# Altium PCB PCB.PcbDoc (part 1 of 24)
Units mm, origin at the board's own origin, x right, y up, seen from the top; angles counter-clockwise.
Board outline 100 x 160 mm, 10 copper layers (TOP_L1, L2, L3, L4, L5, L6, L7, L8, L9, BOTTOM_L10), stack 1.946 mm thick; 1358 components, 1149 nets, 6777 pads, 10914 vias.
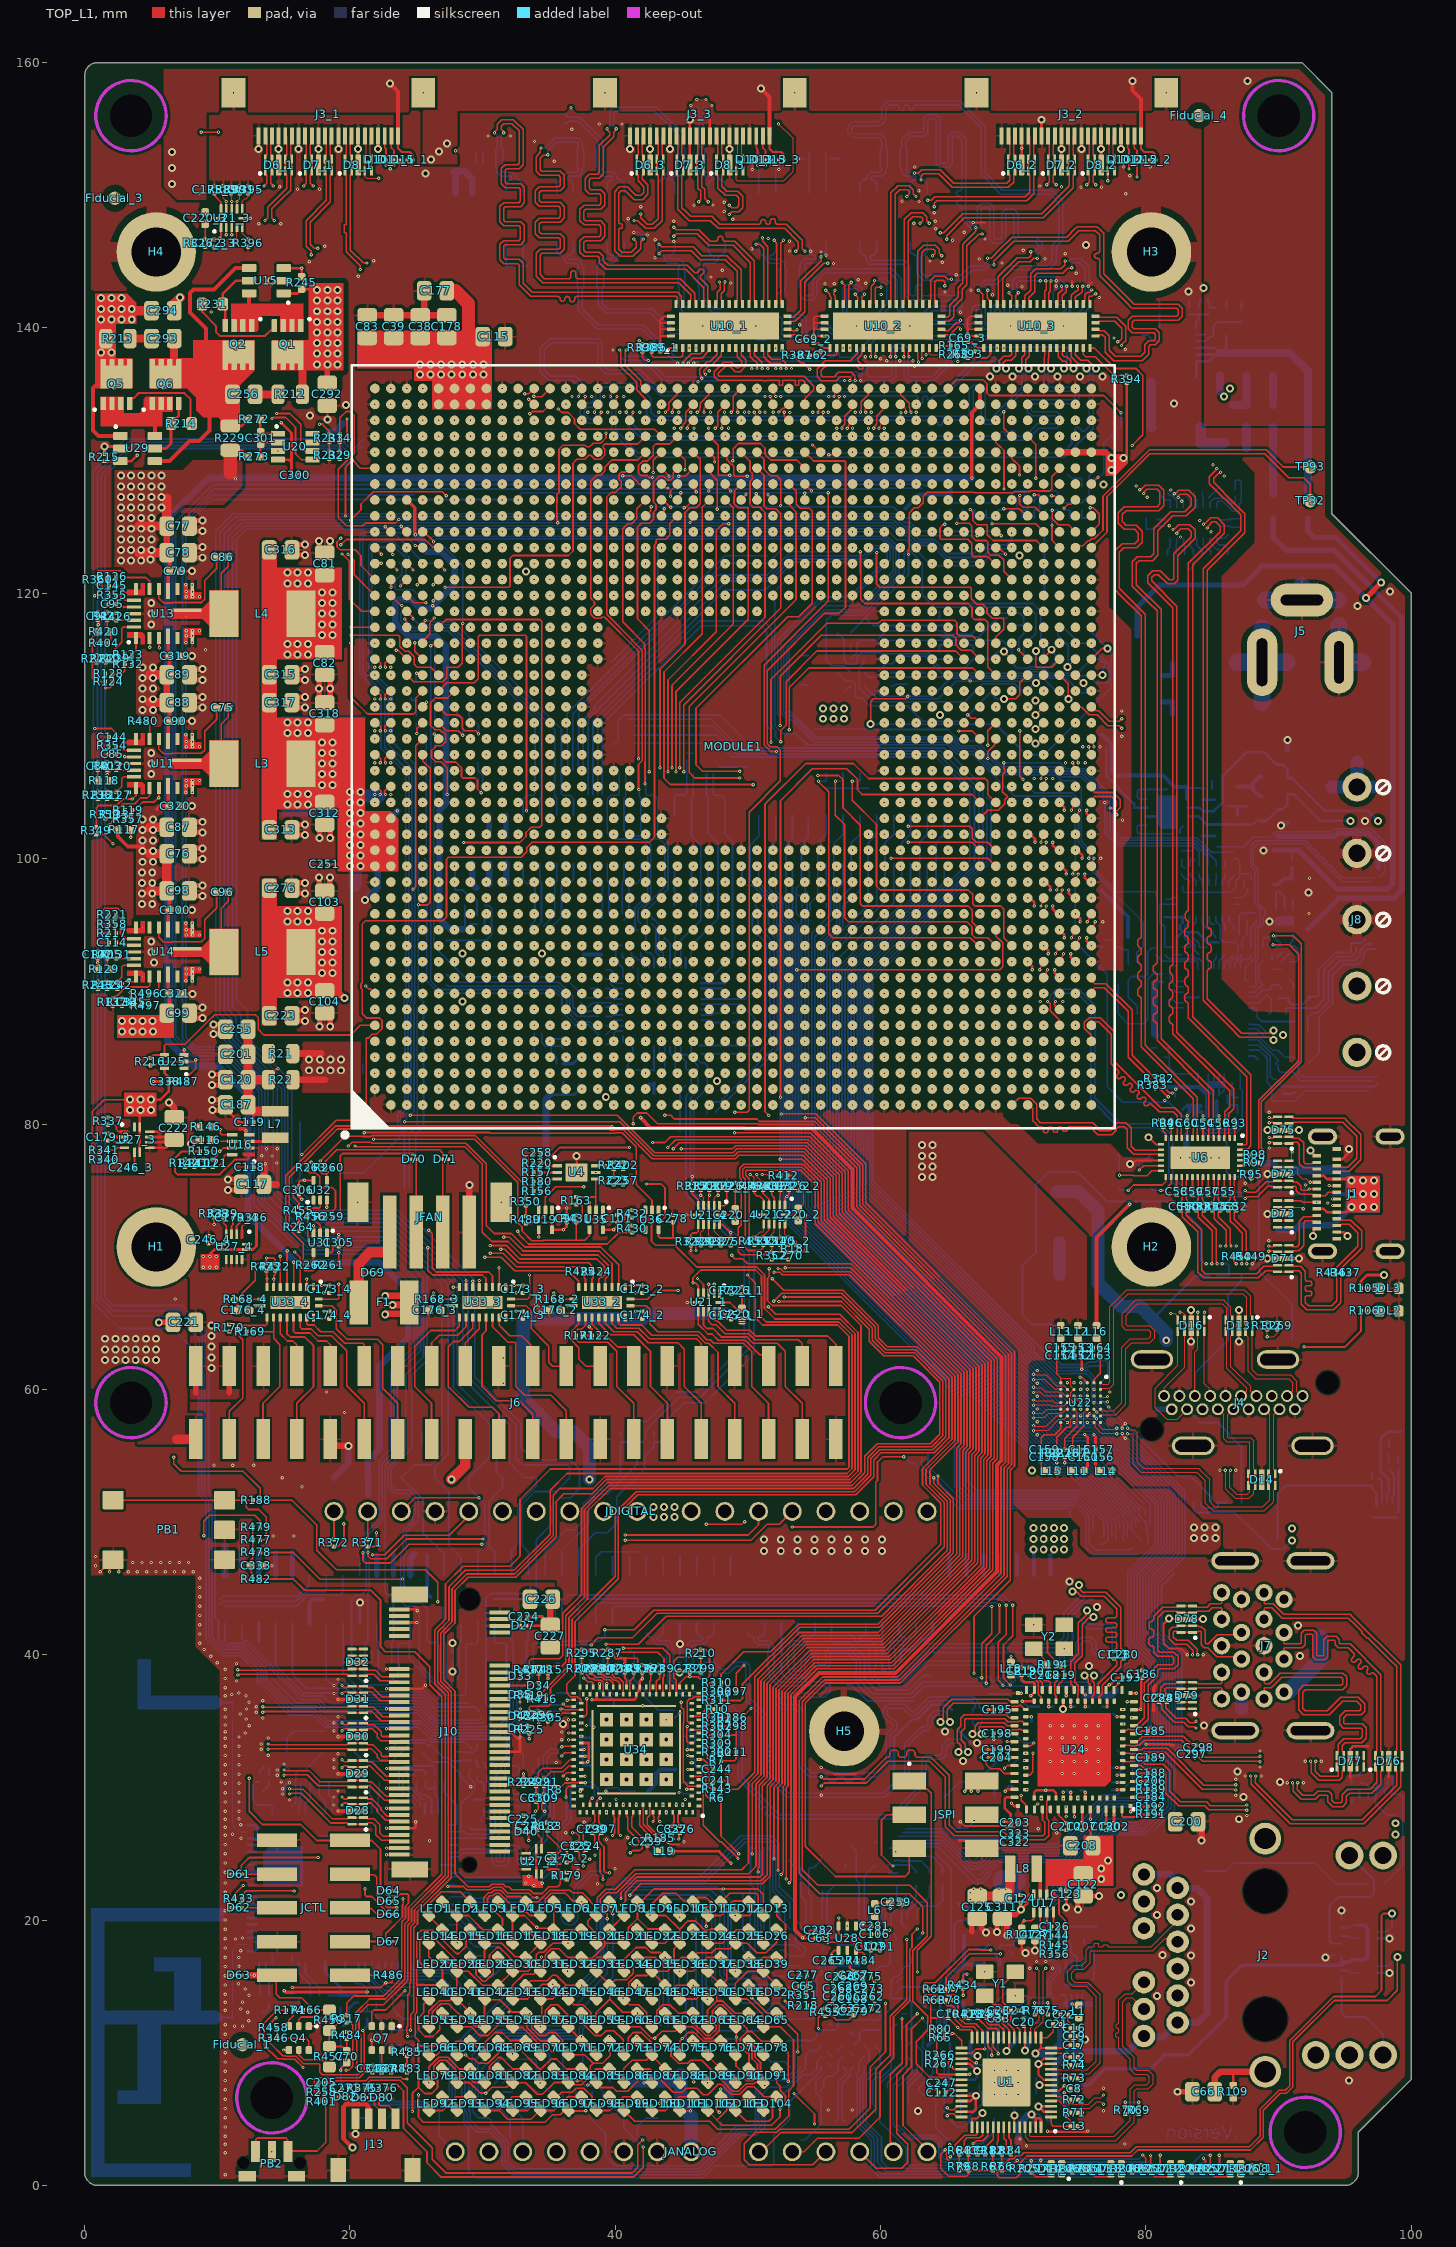
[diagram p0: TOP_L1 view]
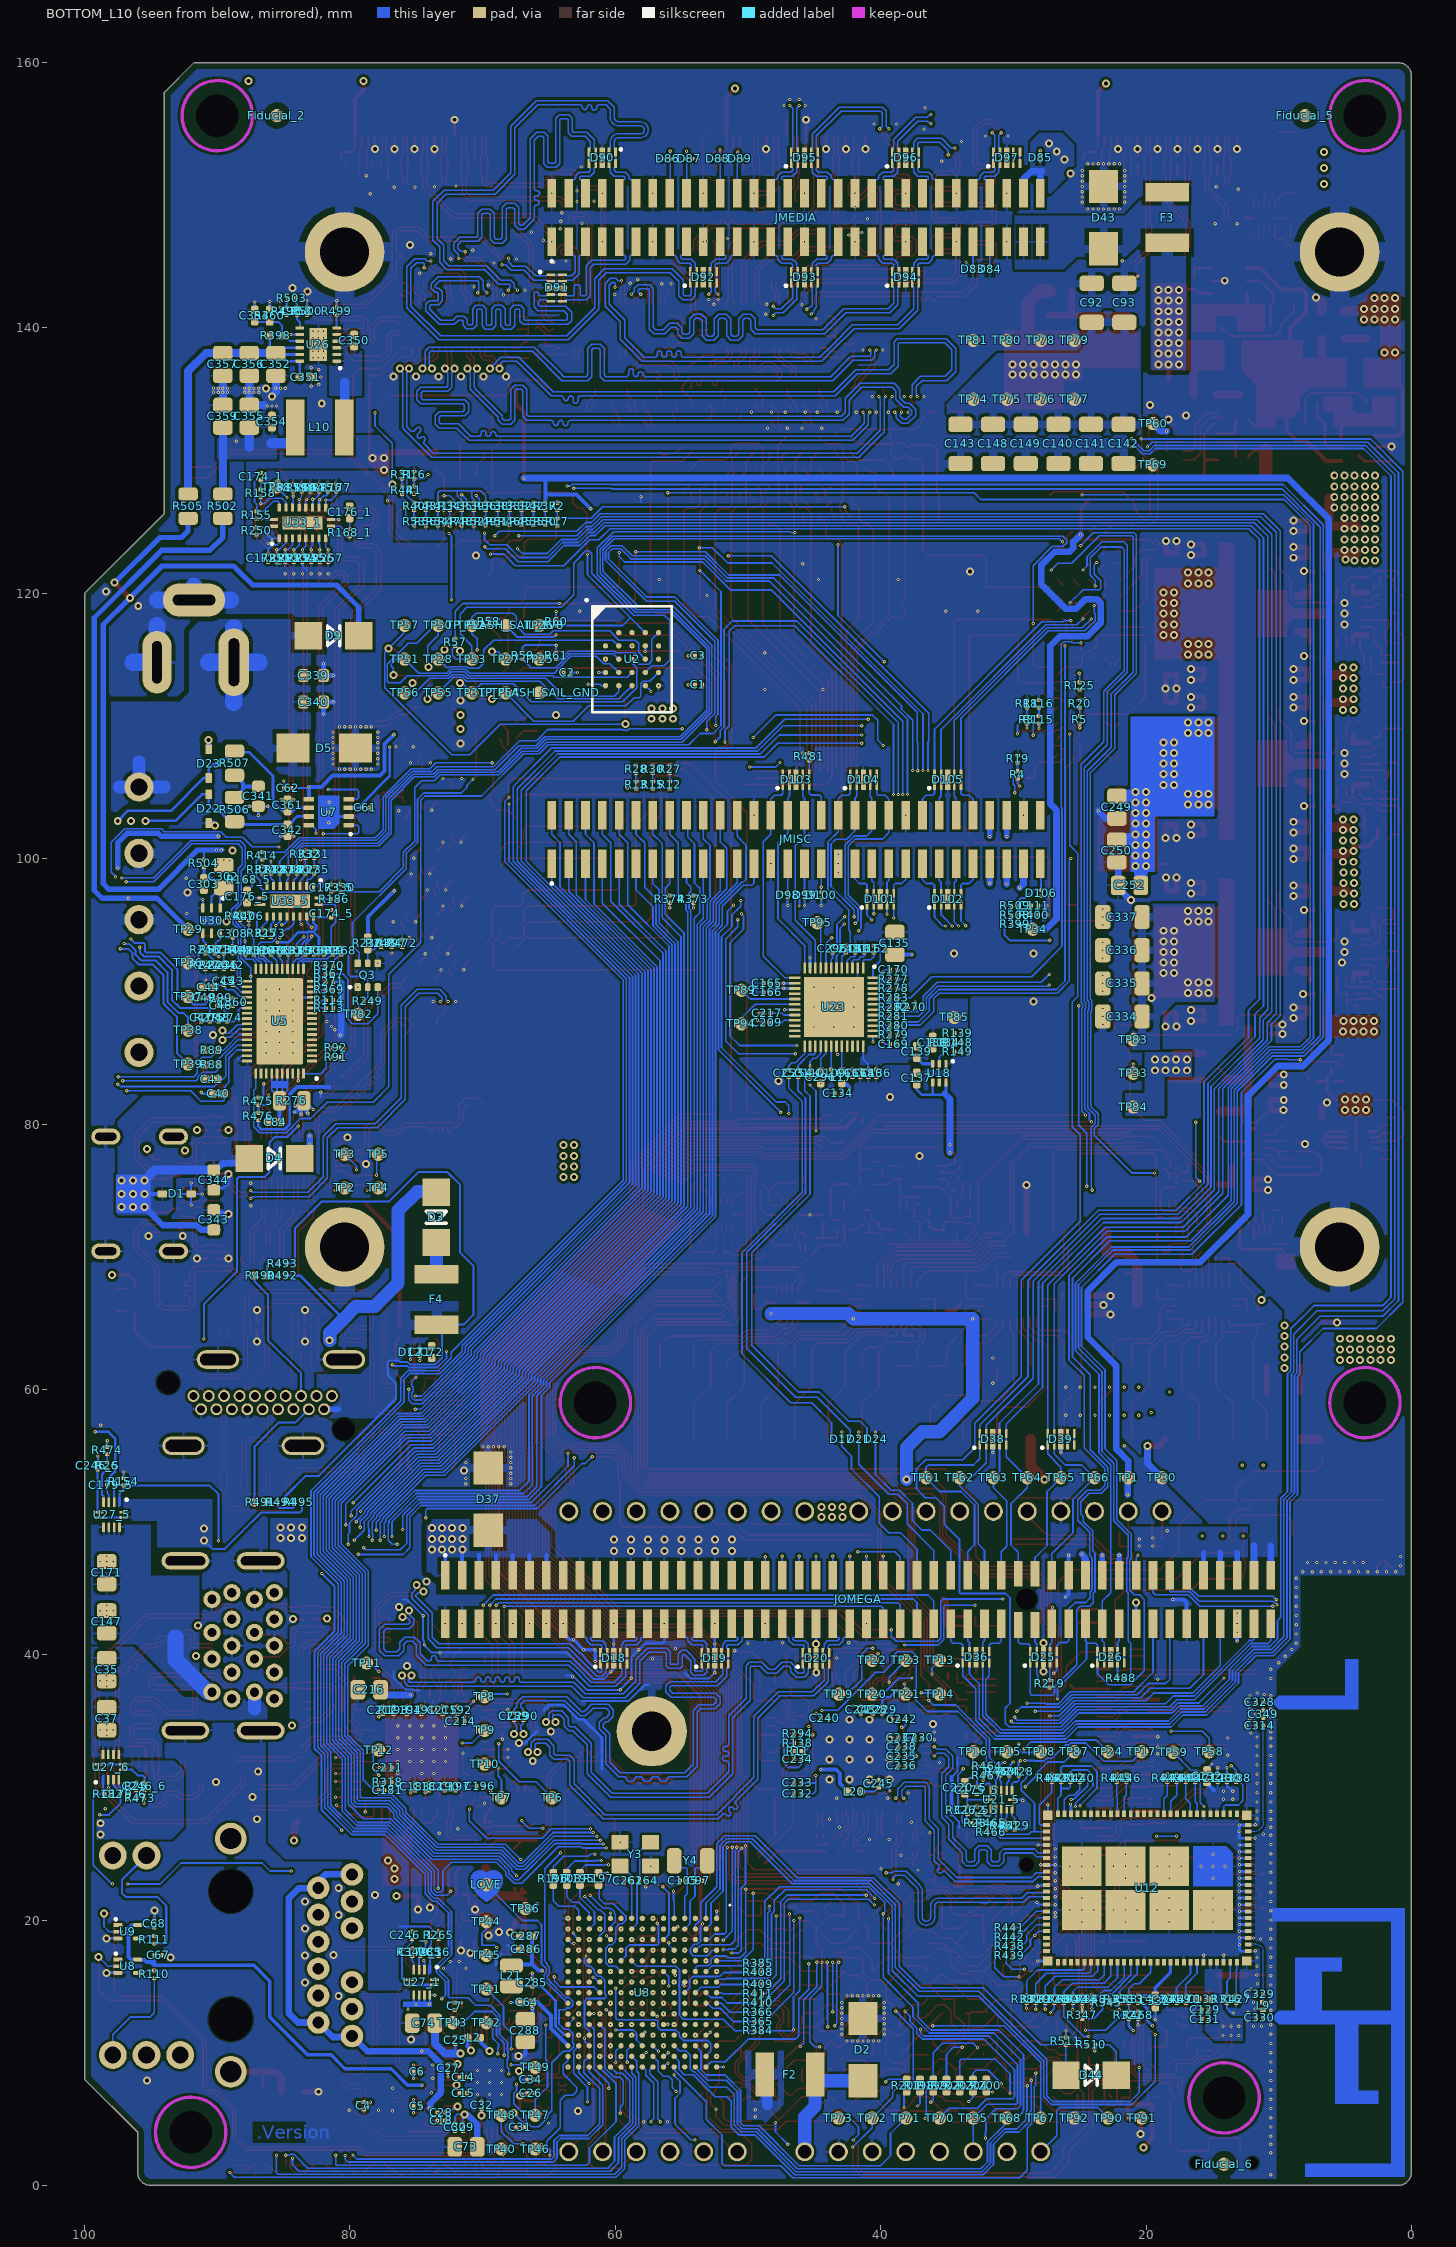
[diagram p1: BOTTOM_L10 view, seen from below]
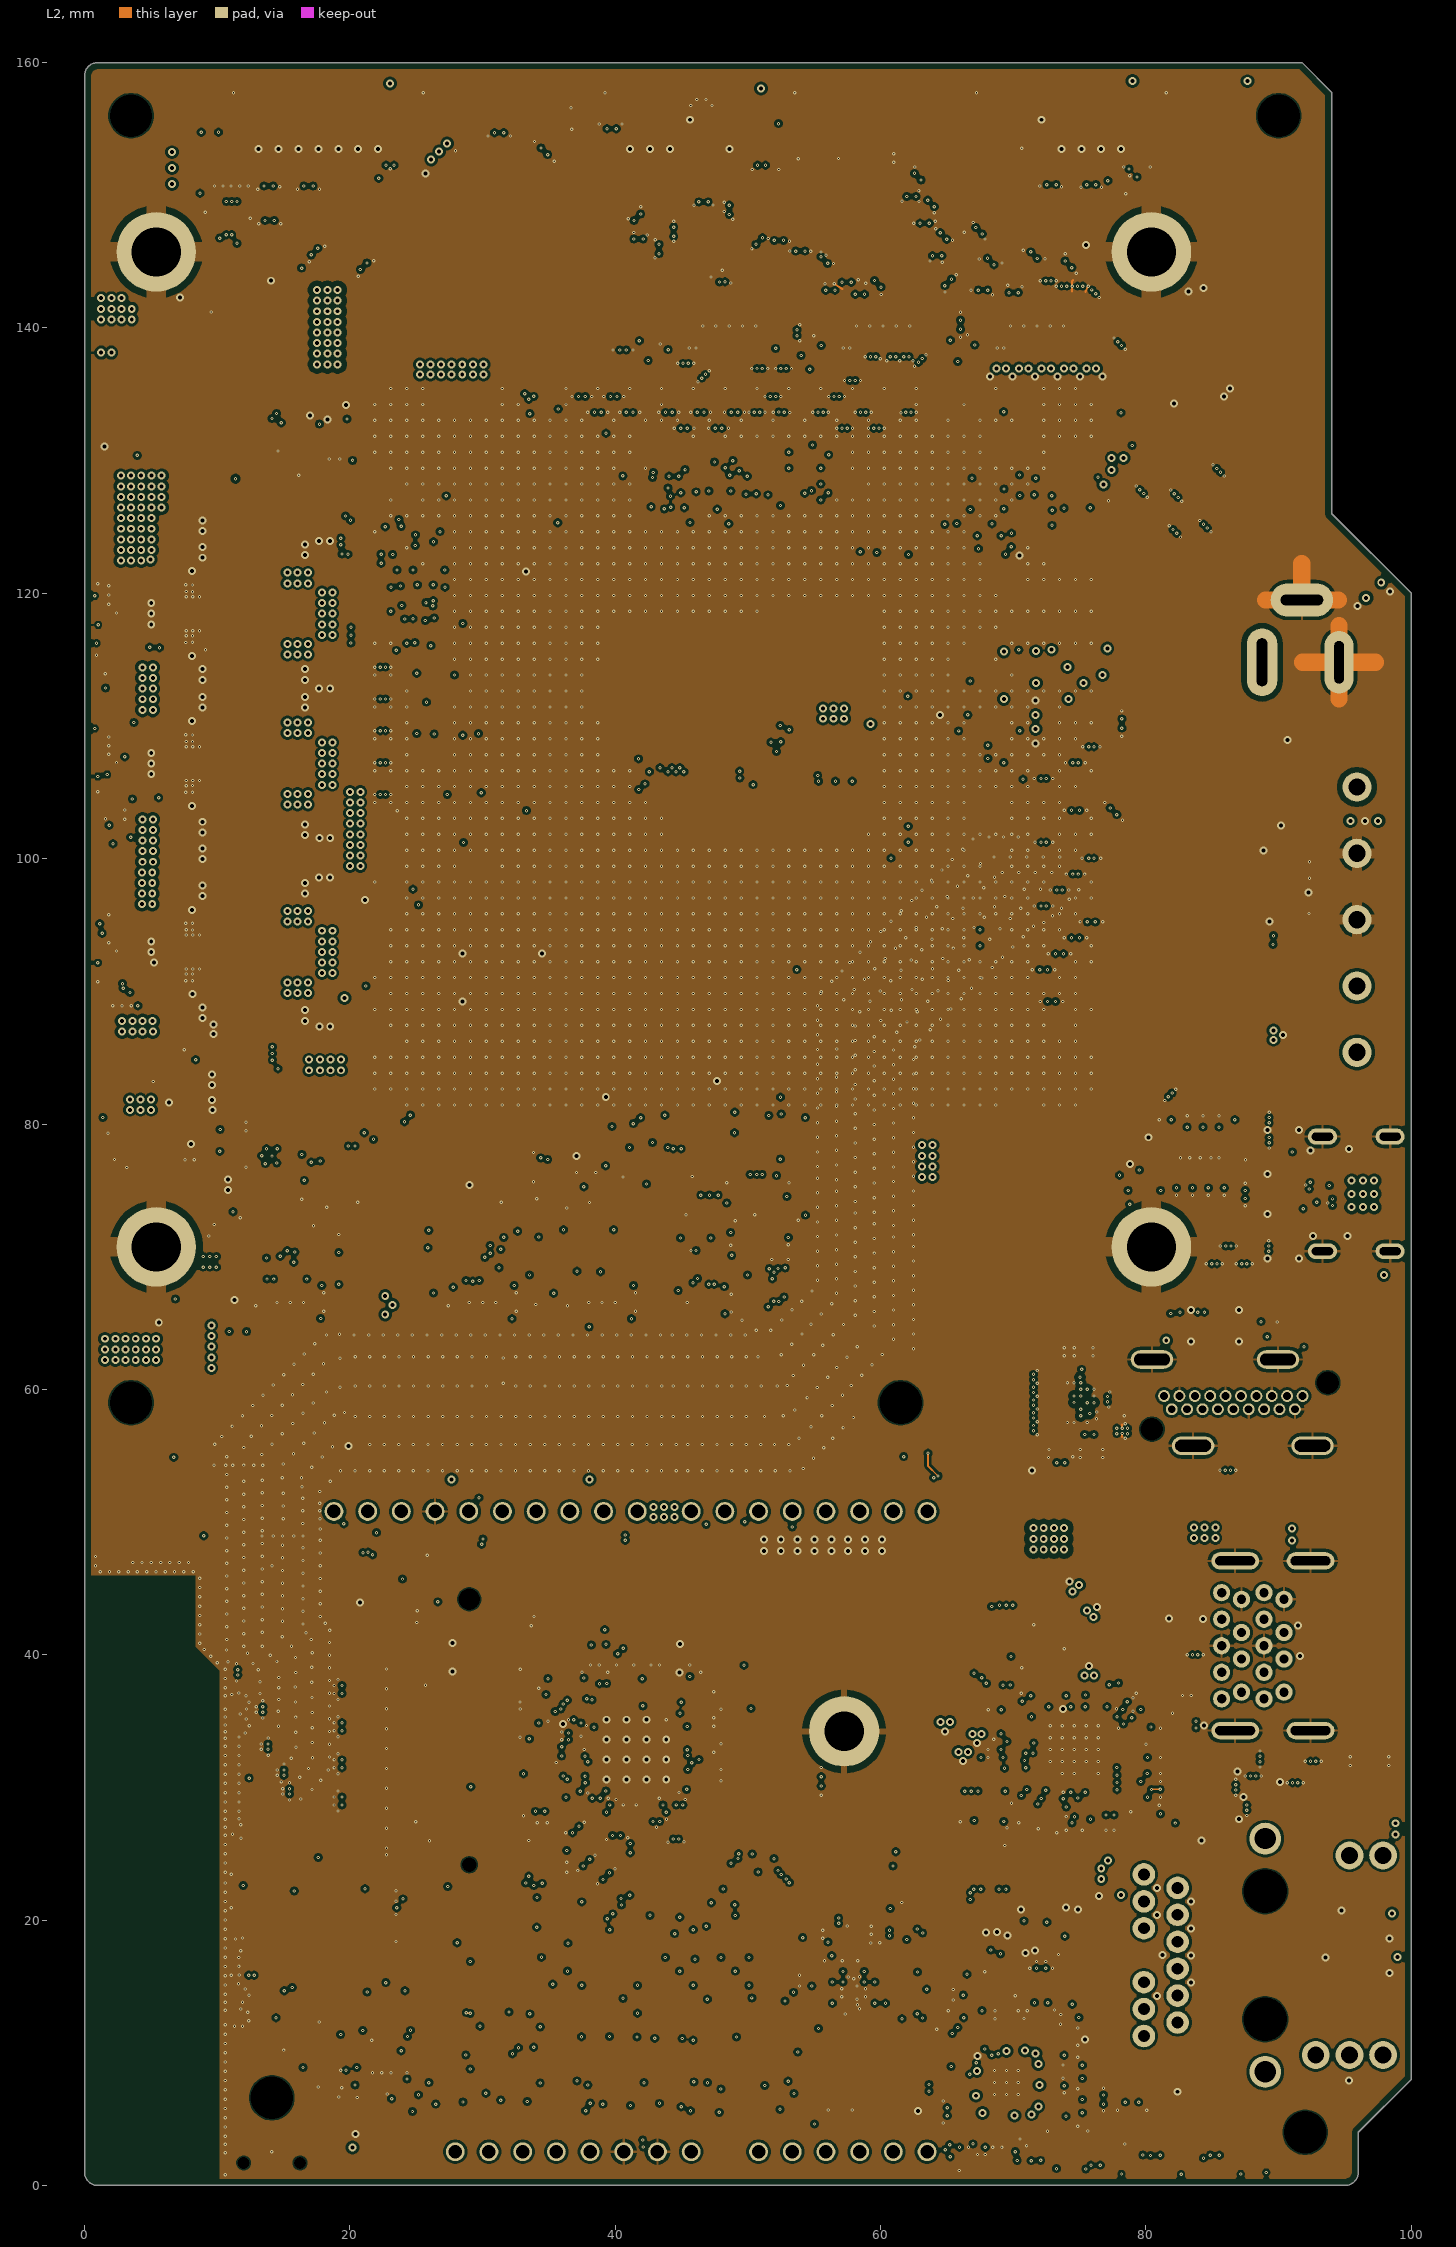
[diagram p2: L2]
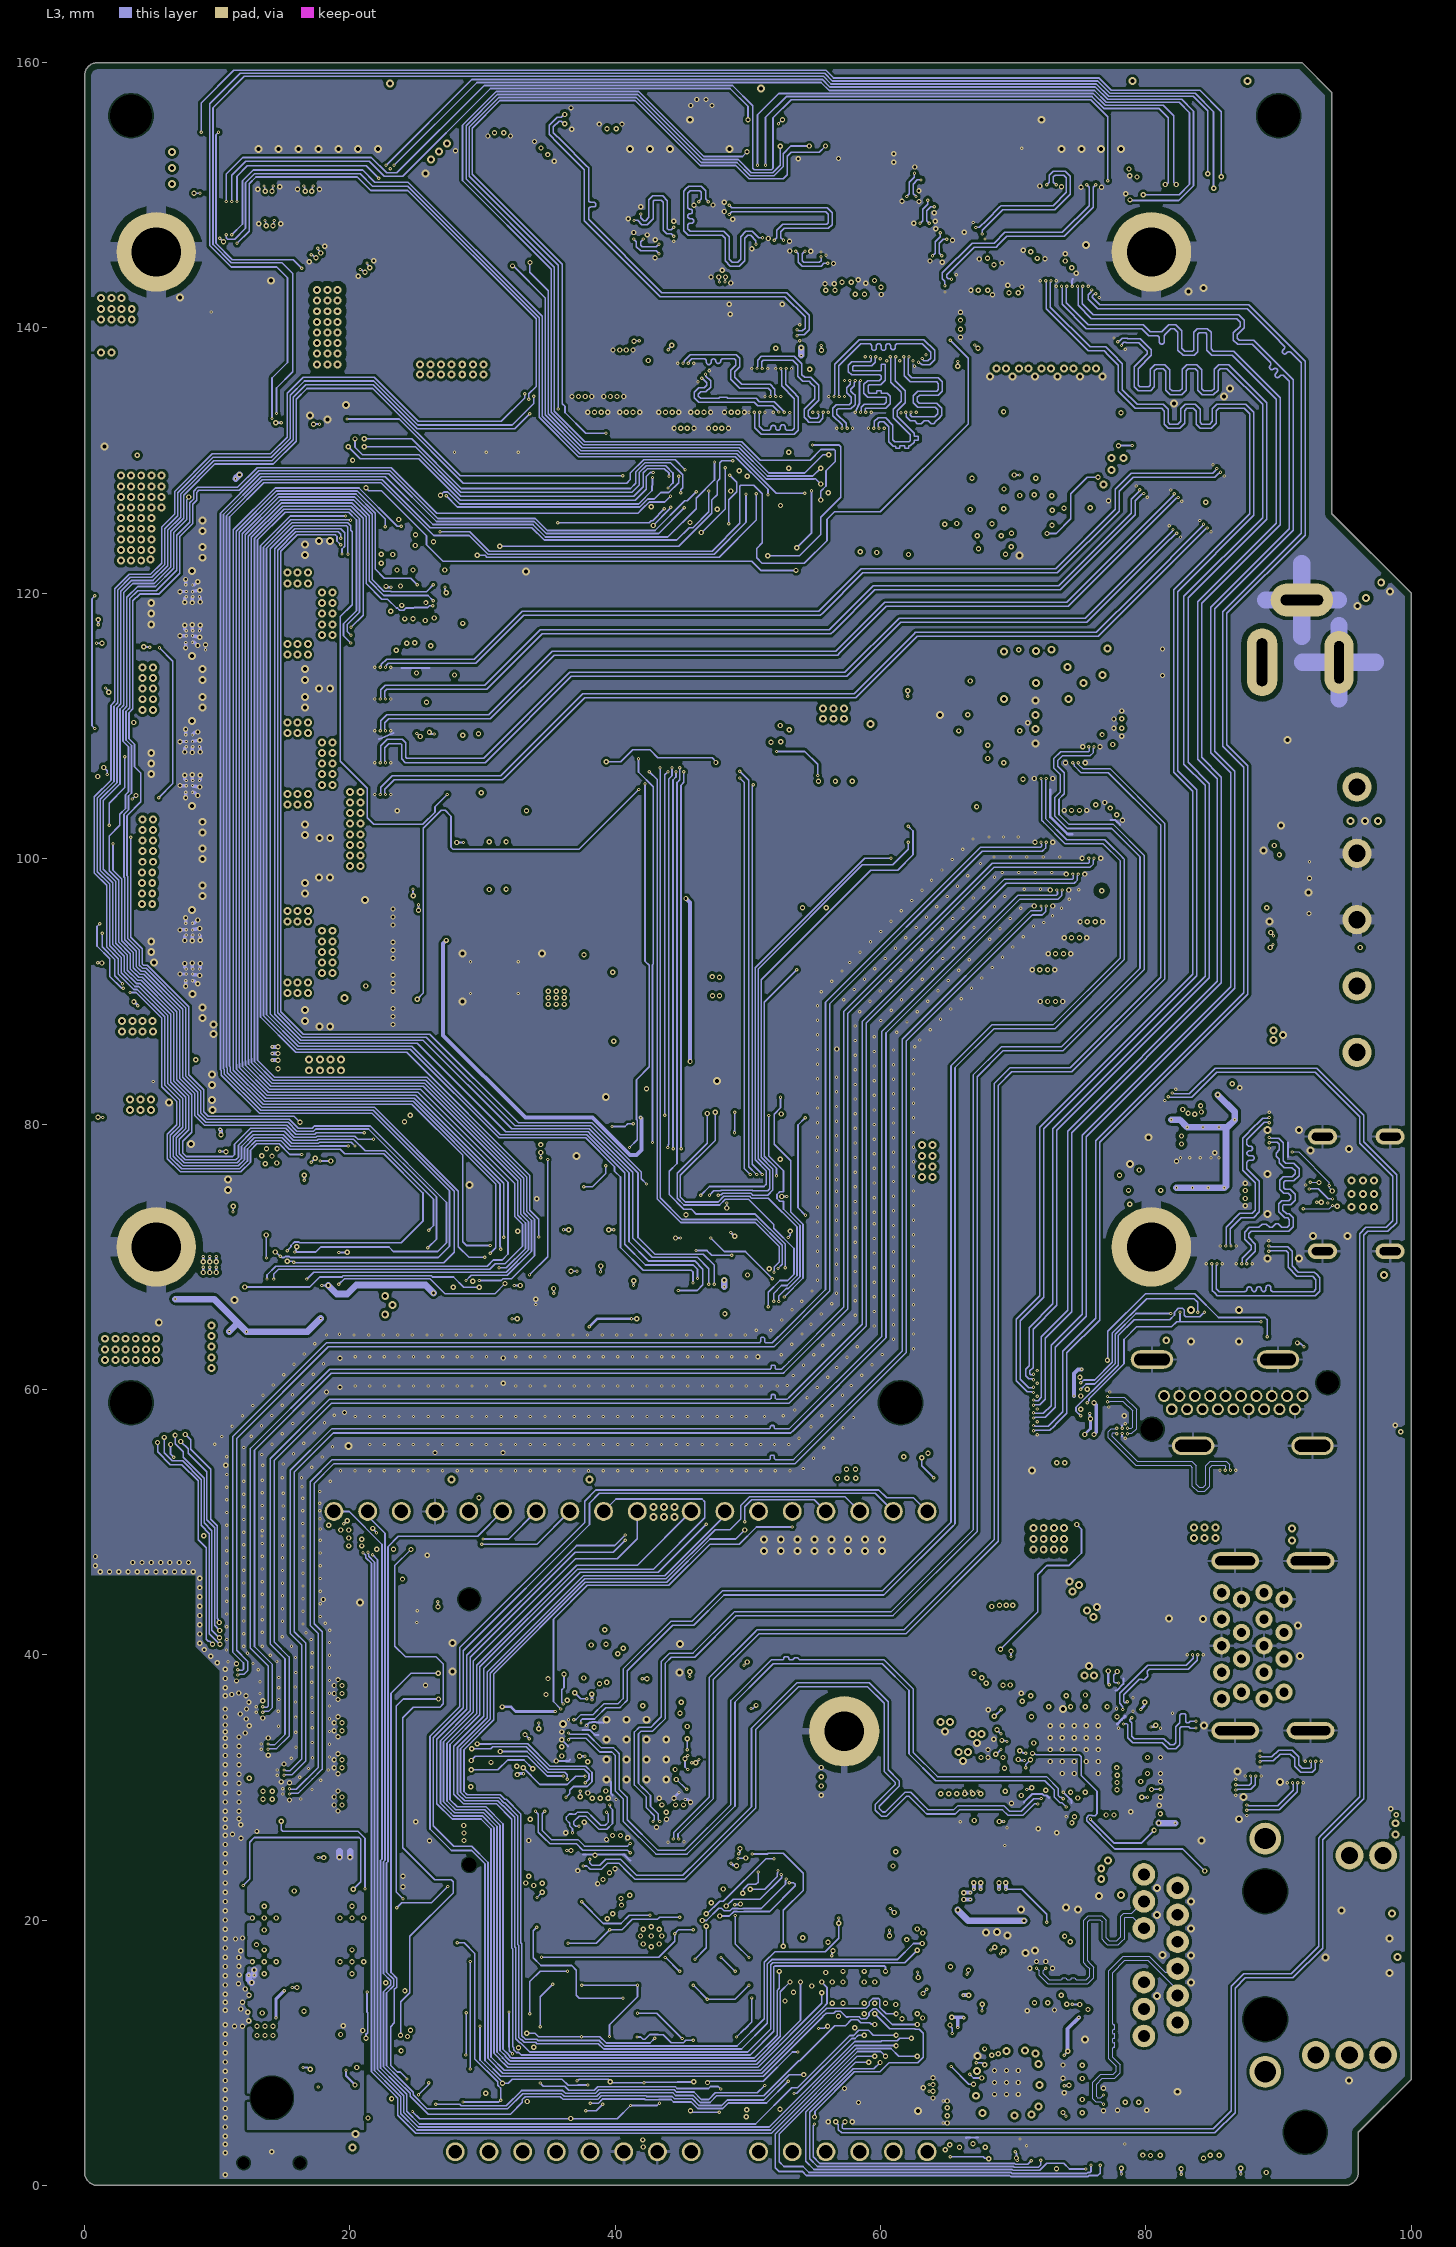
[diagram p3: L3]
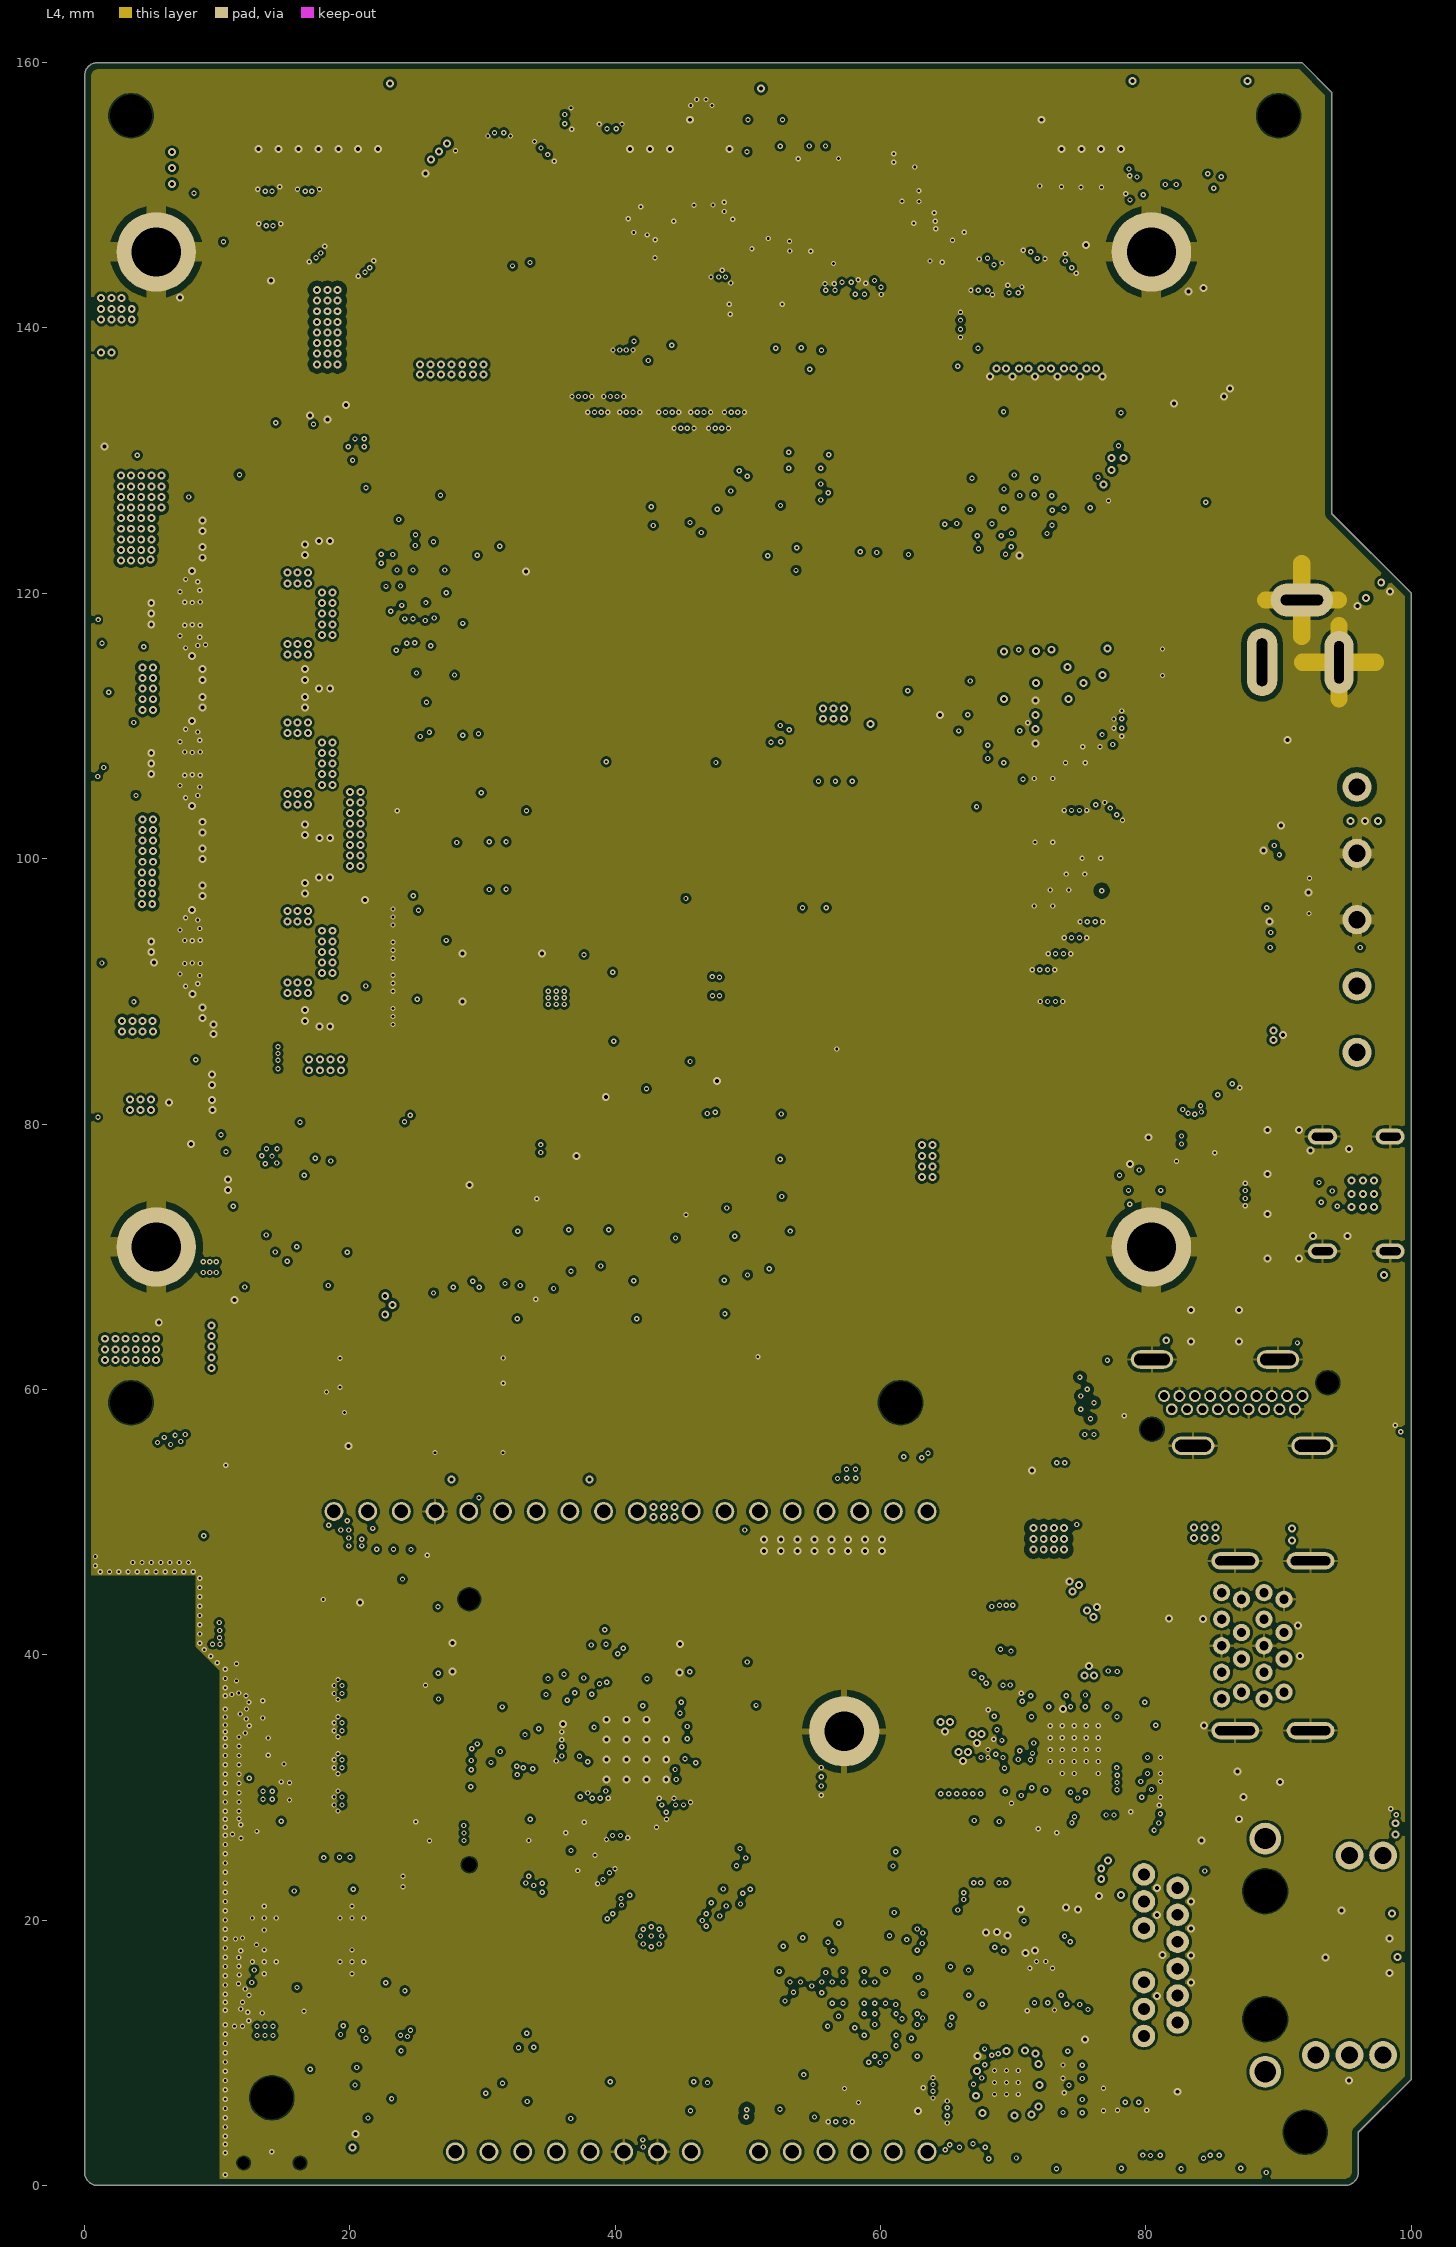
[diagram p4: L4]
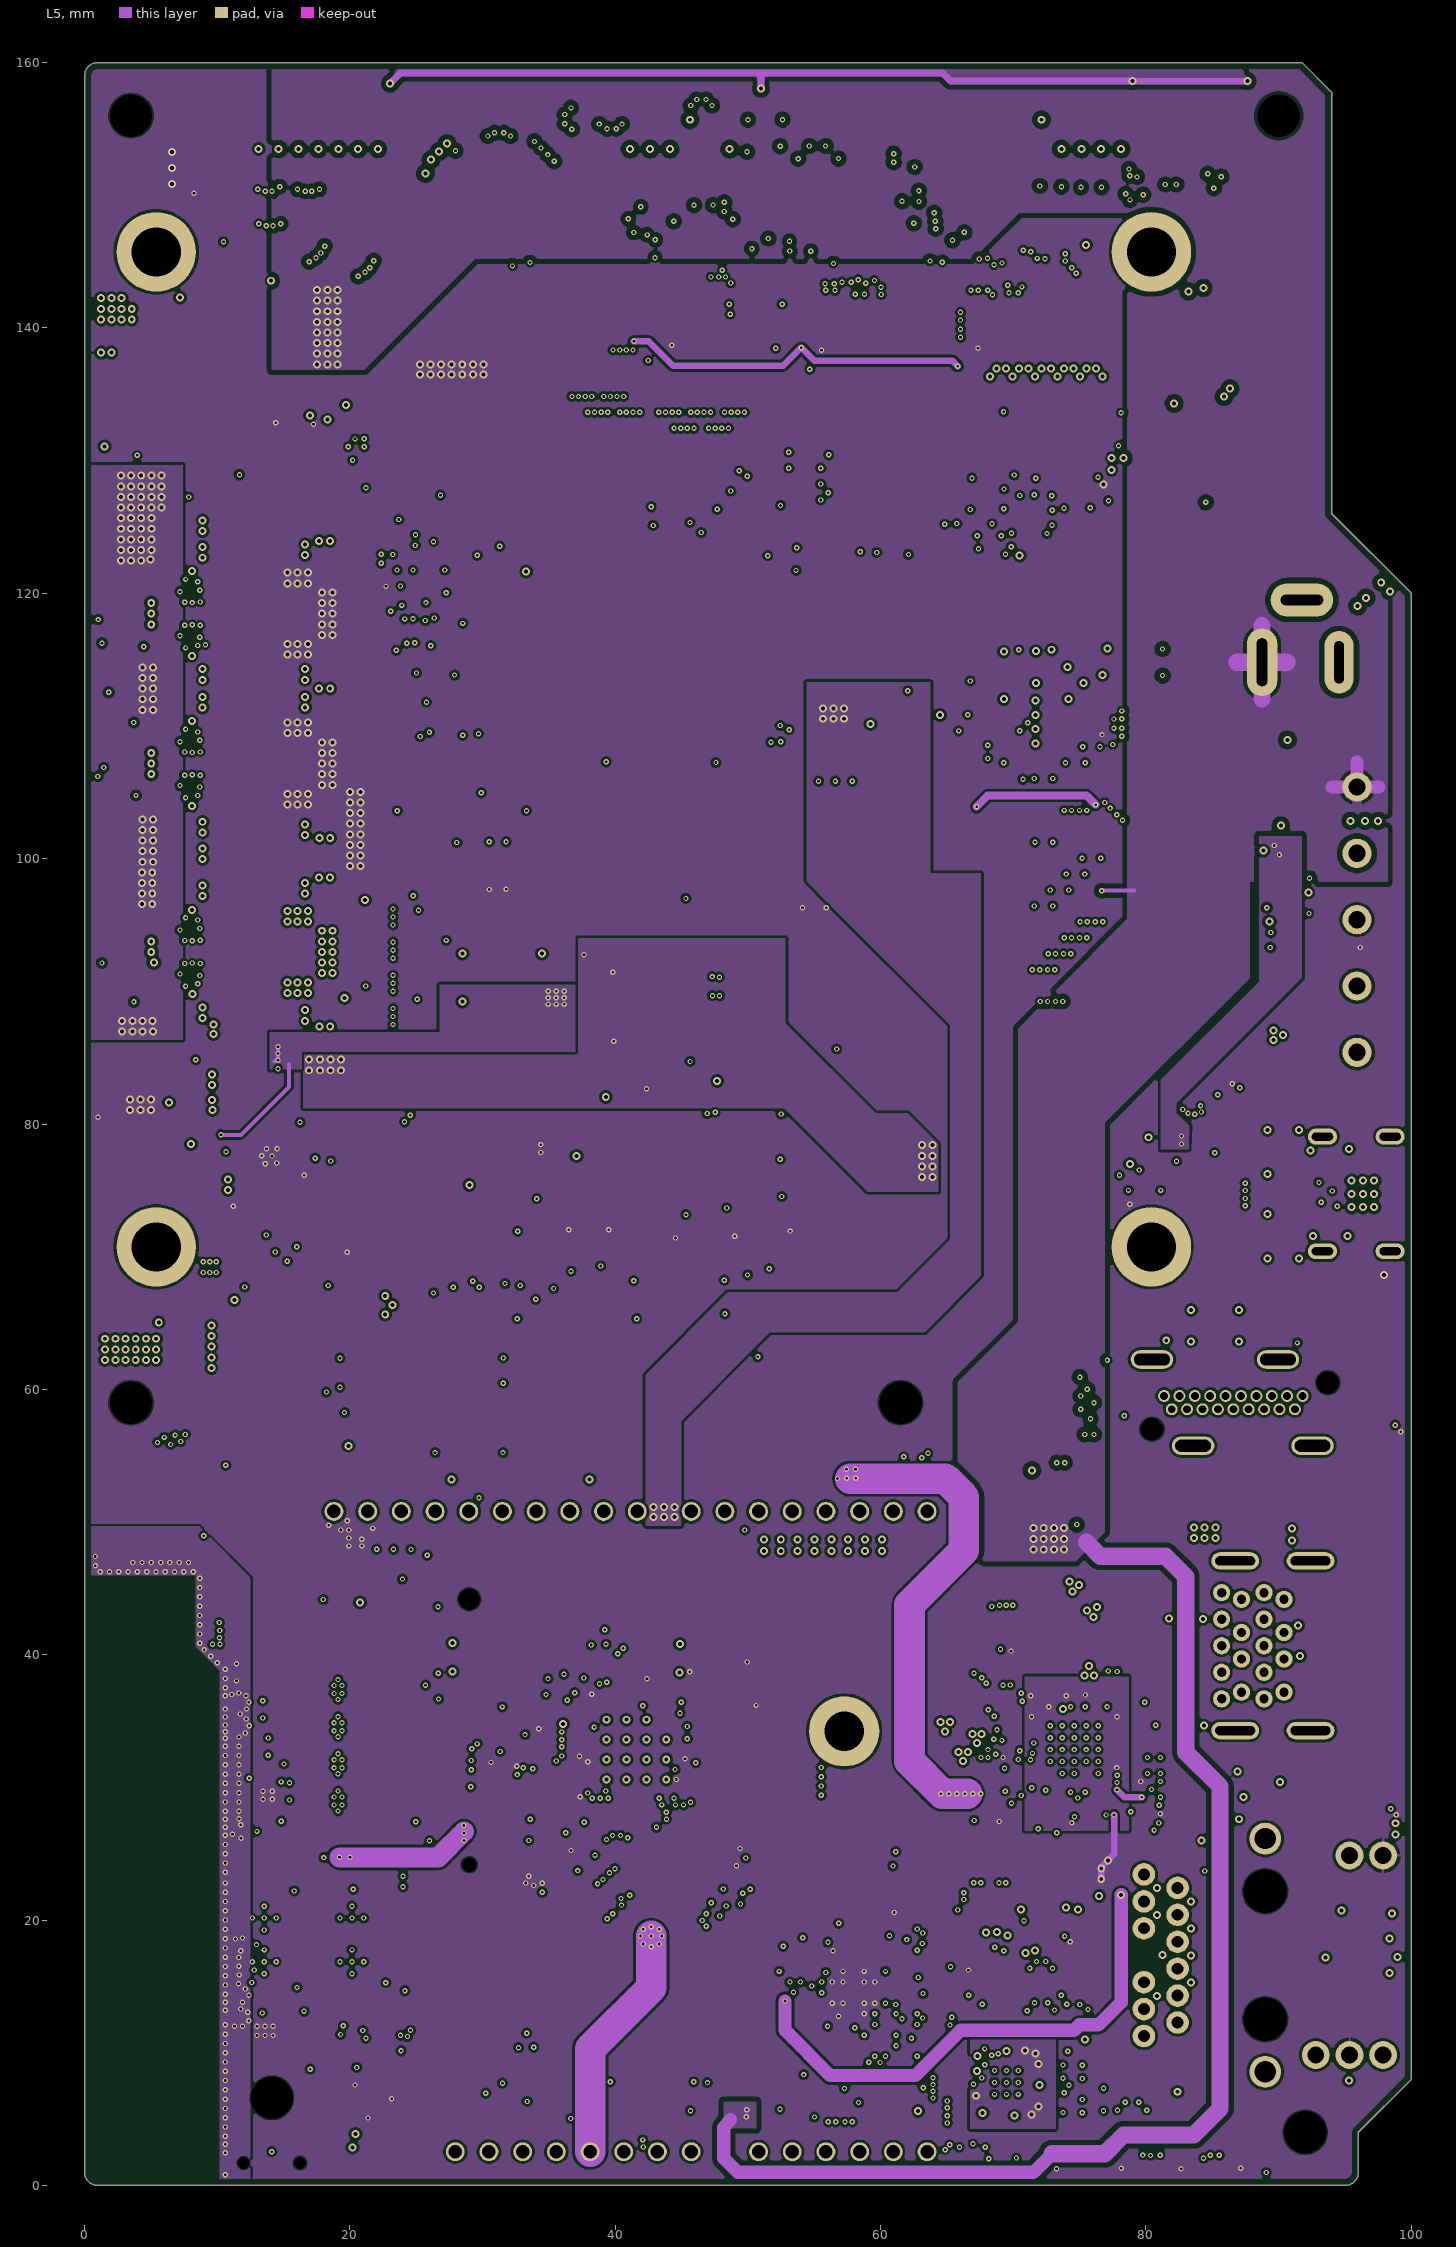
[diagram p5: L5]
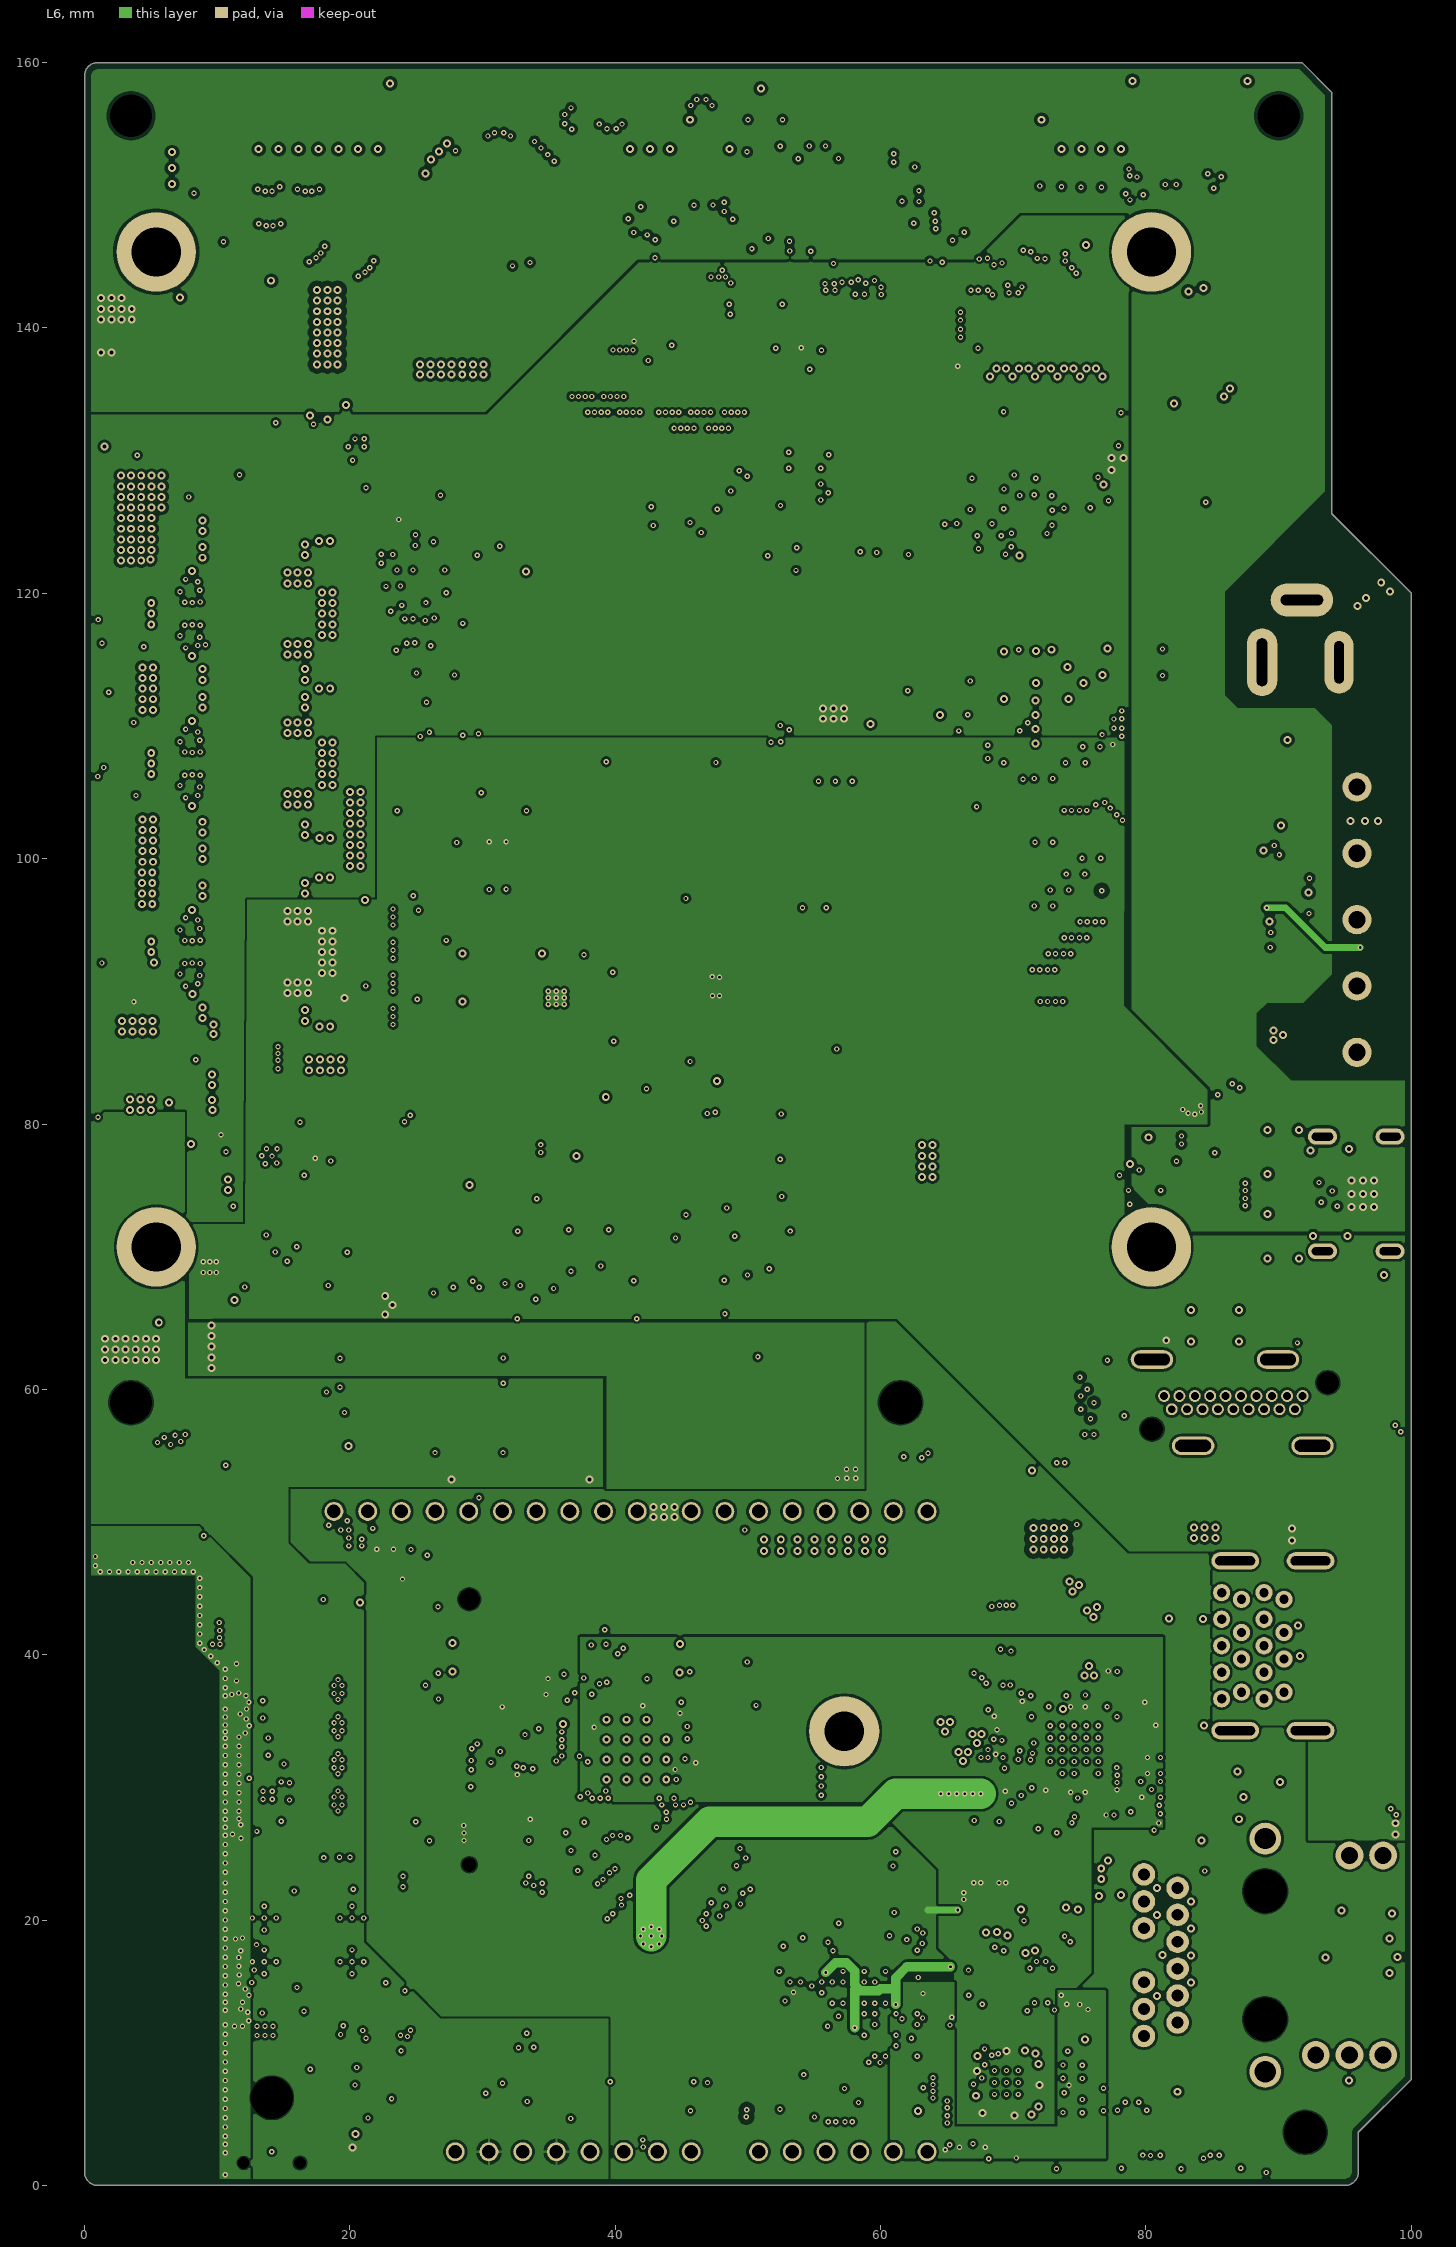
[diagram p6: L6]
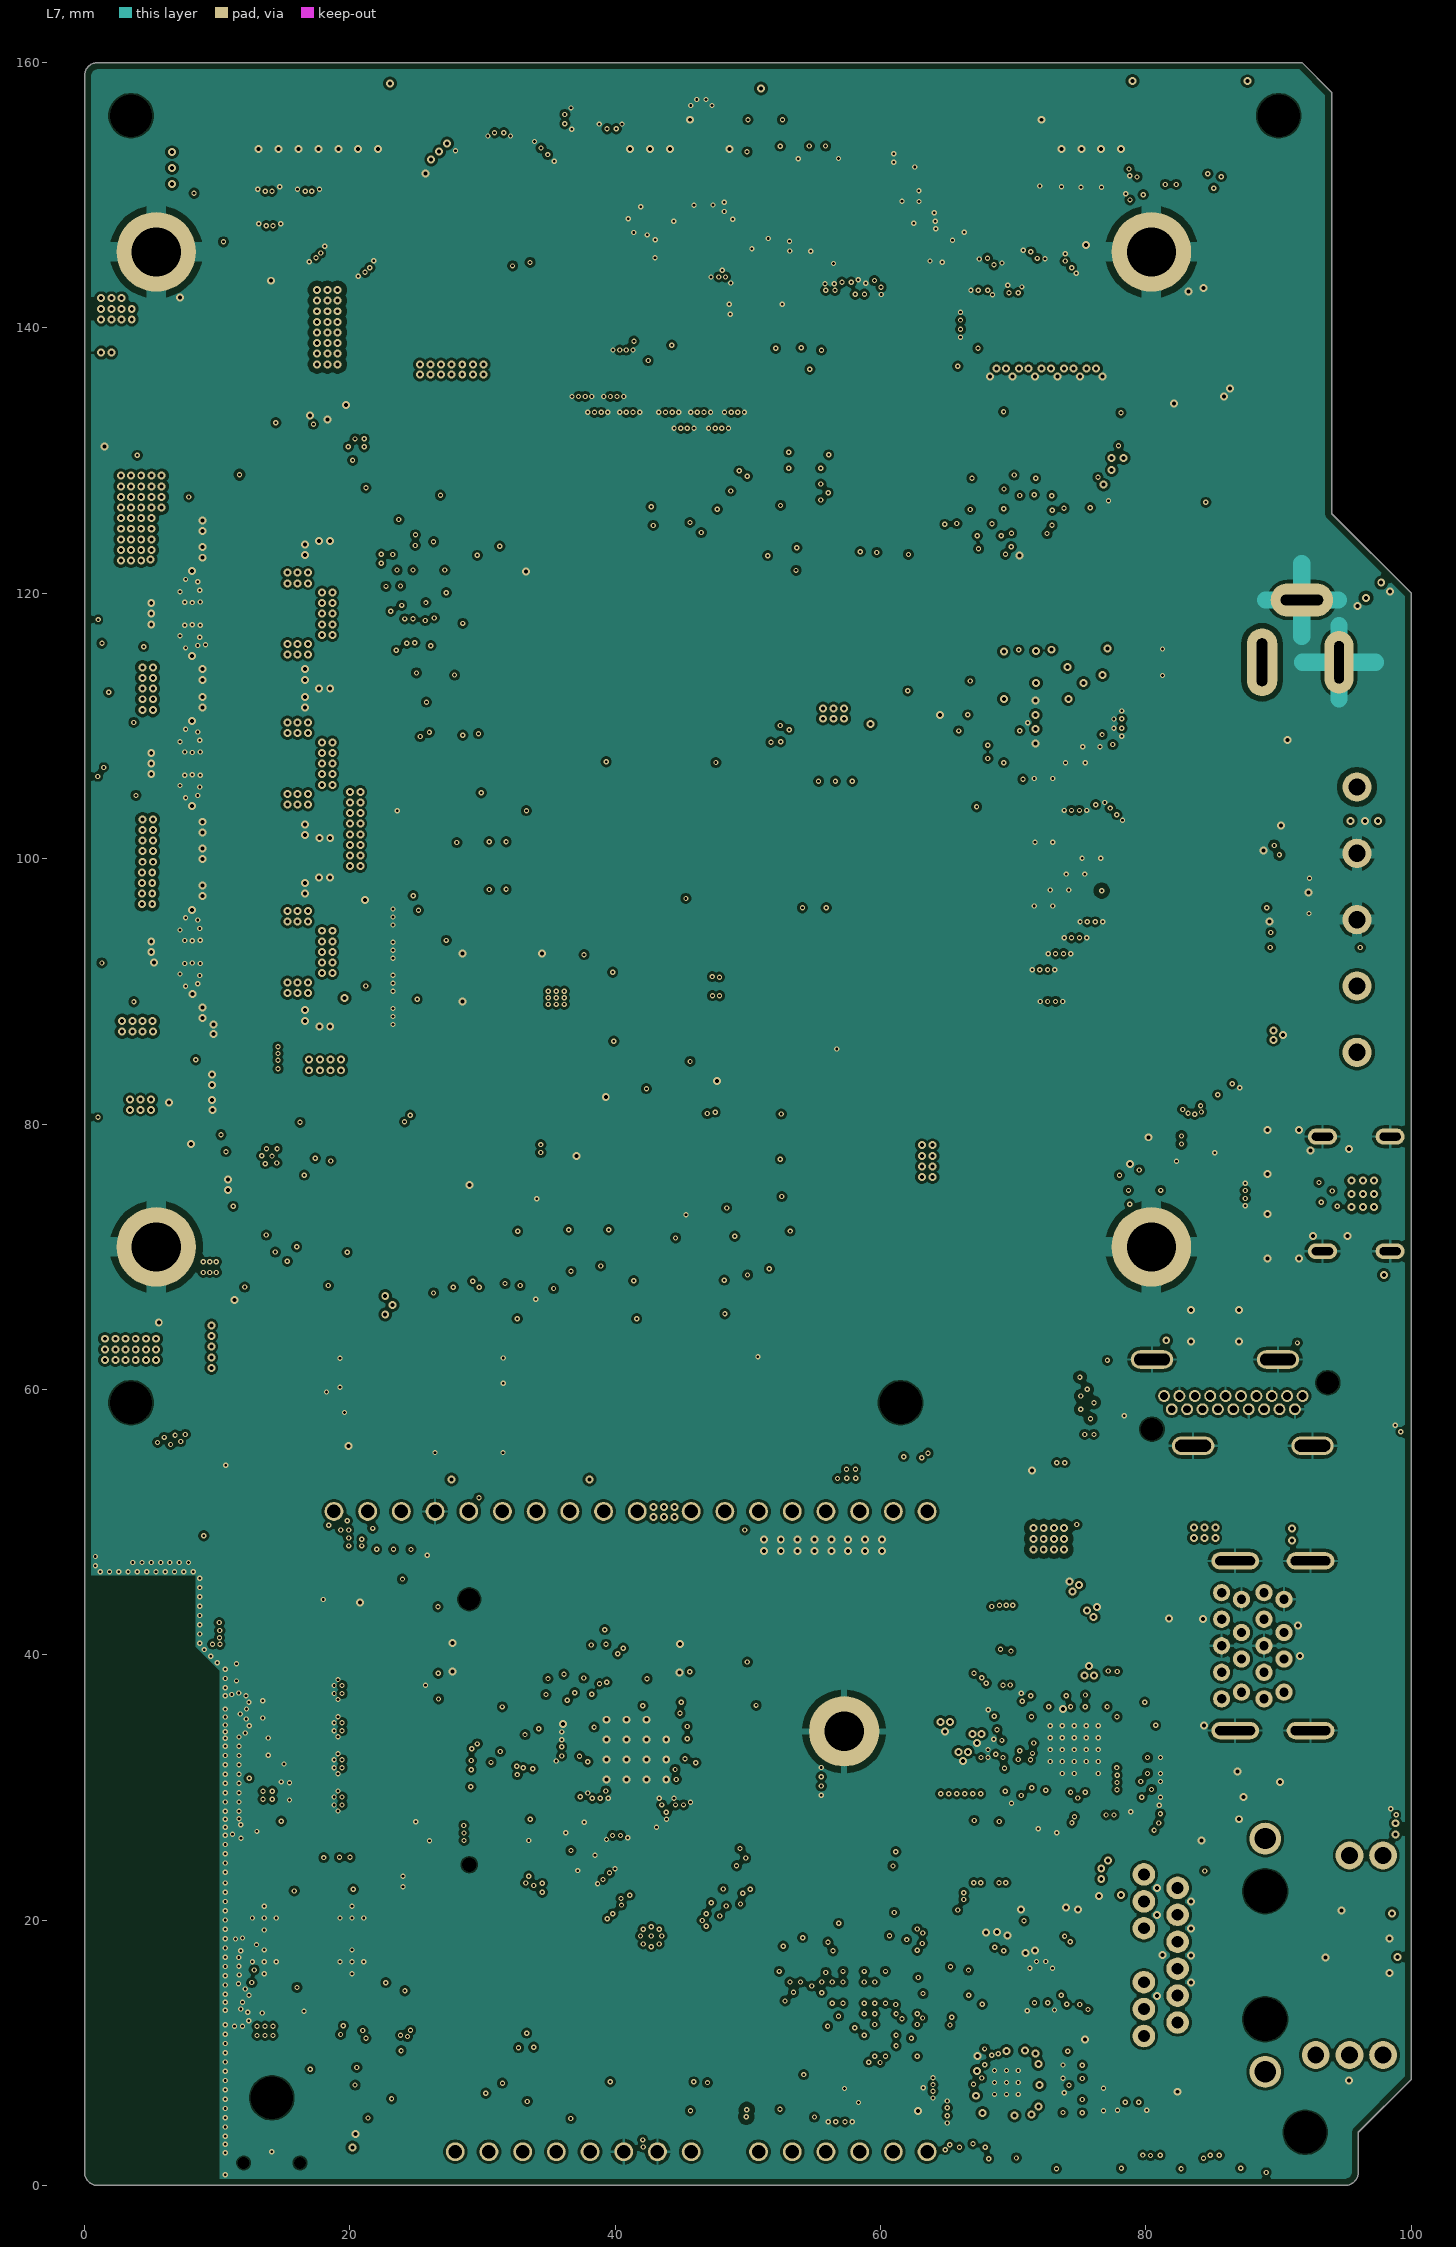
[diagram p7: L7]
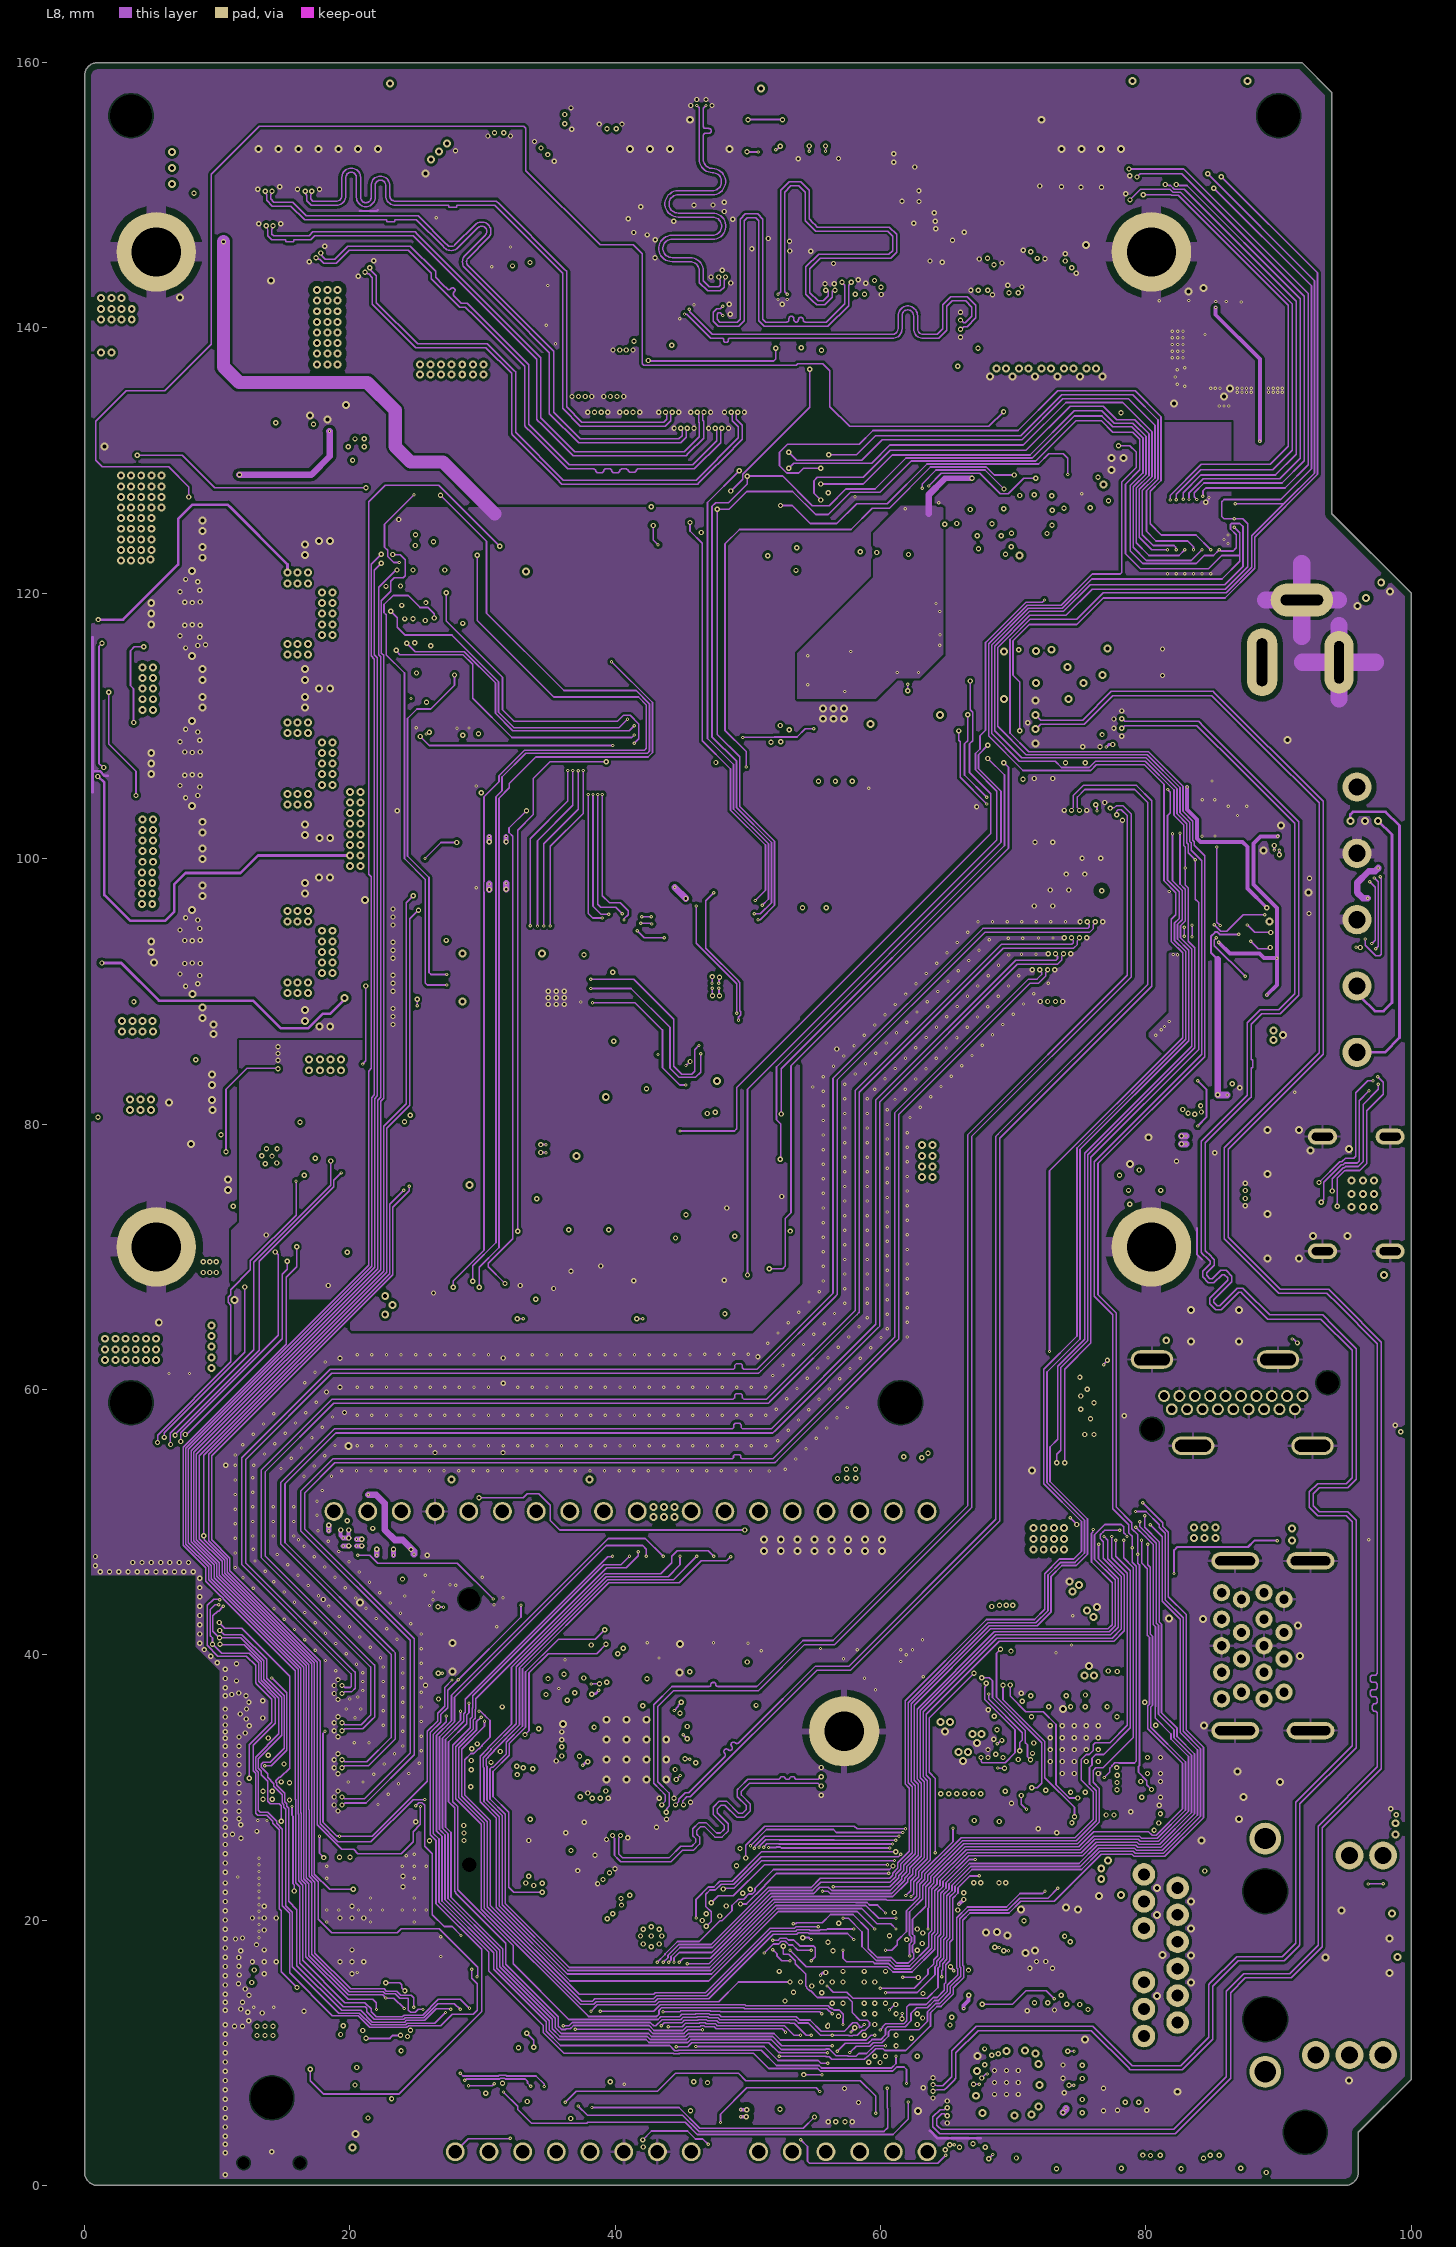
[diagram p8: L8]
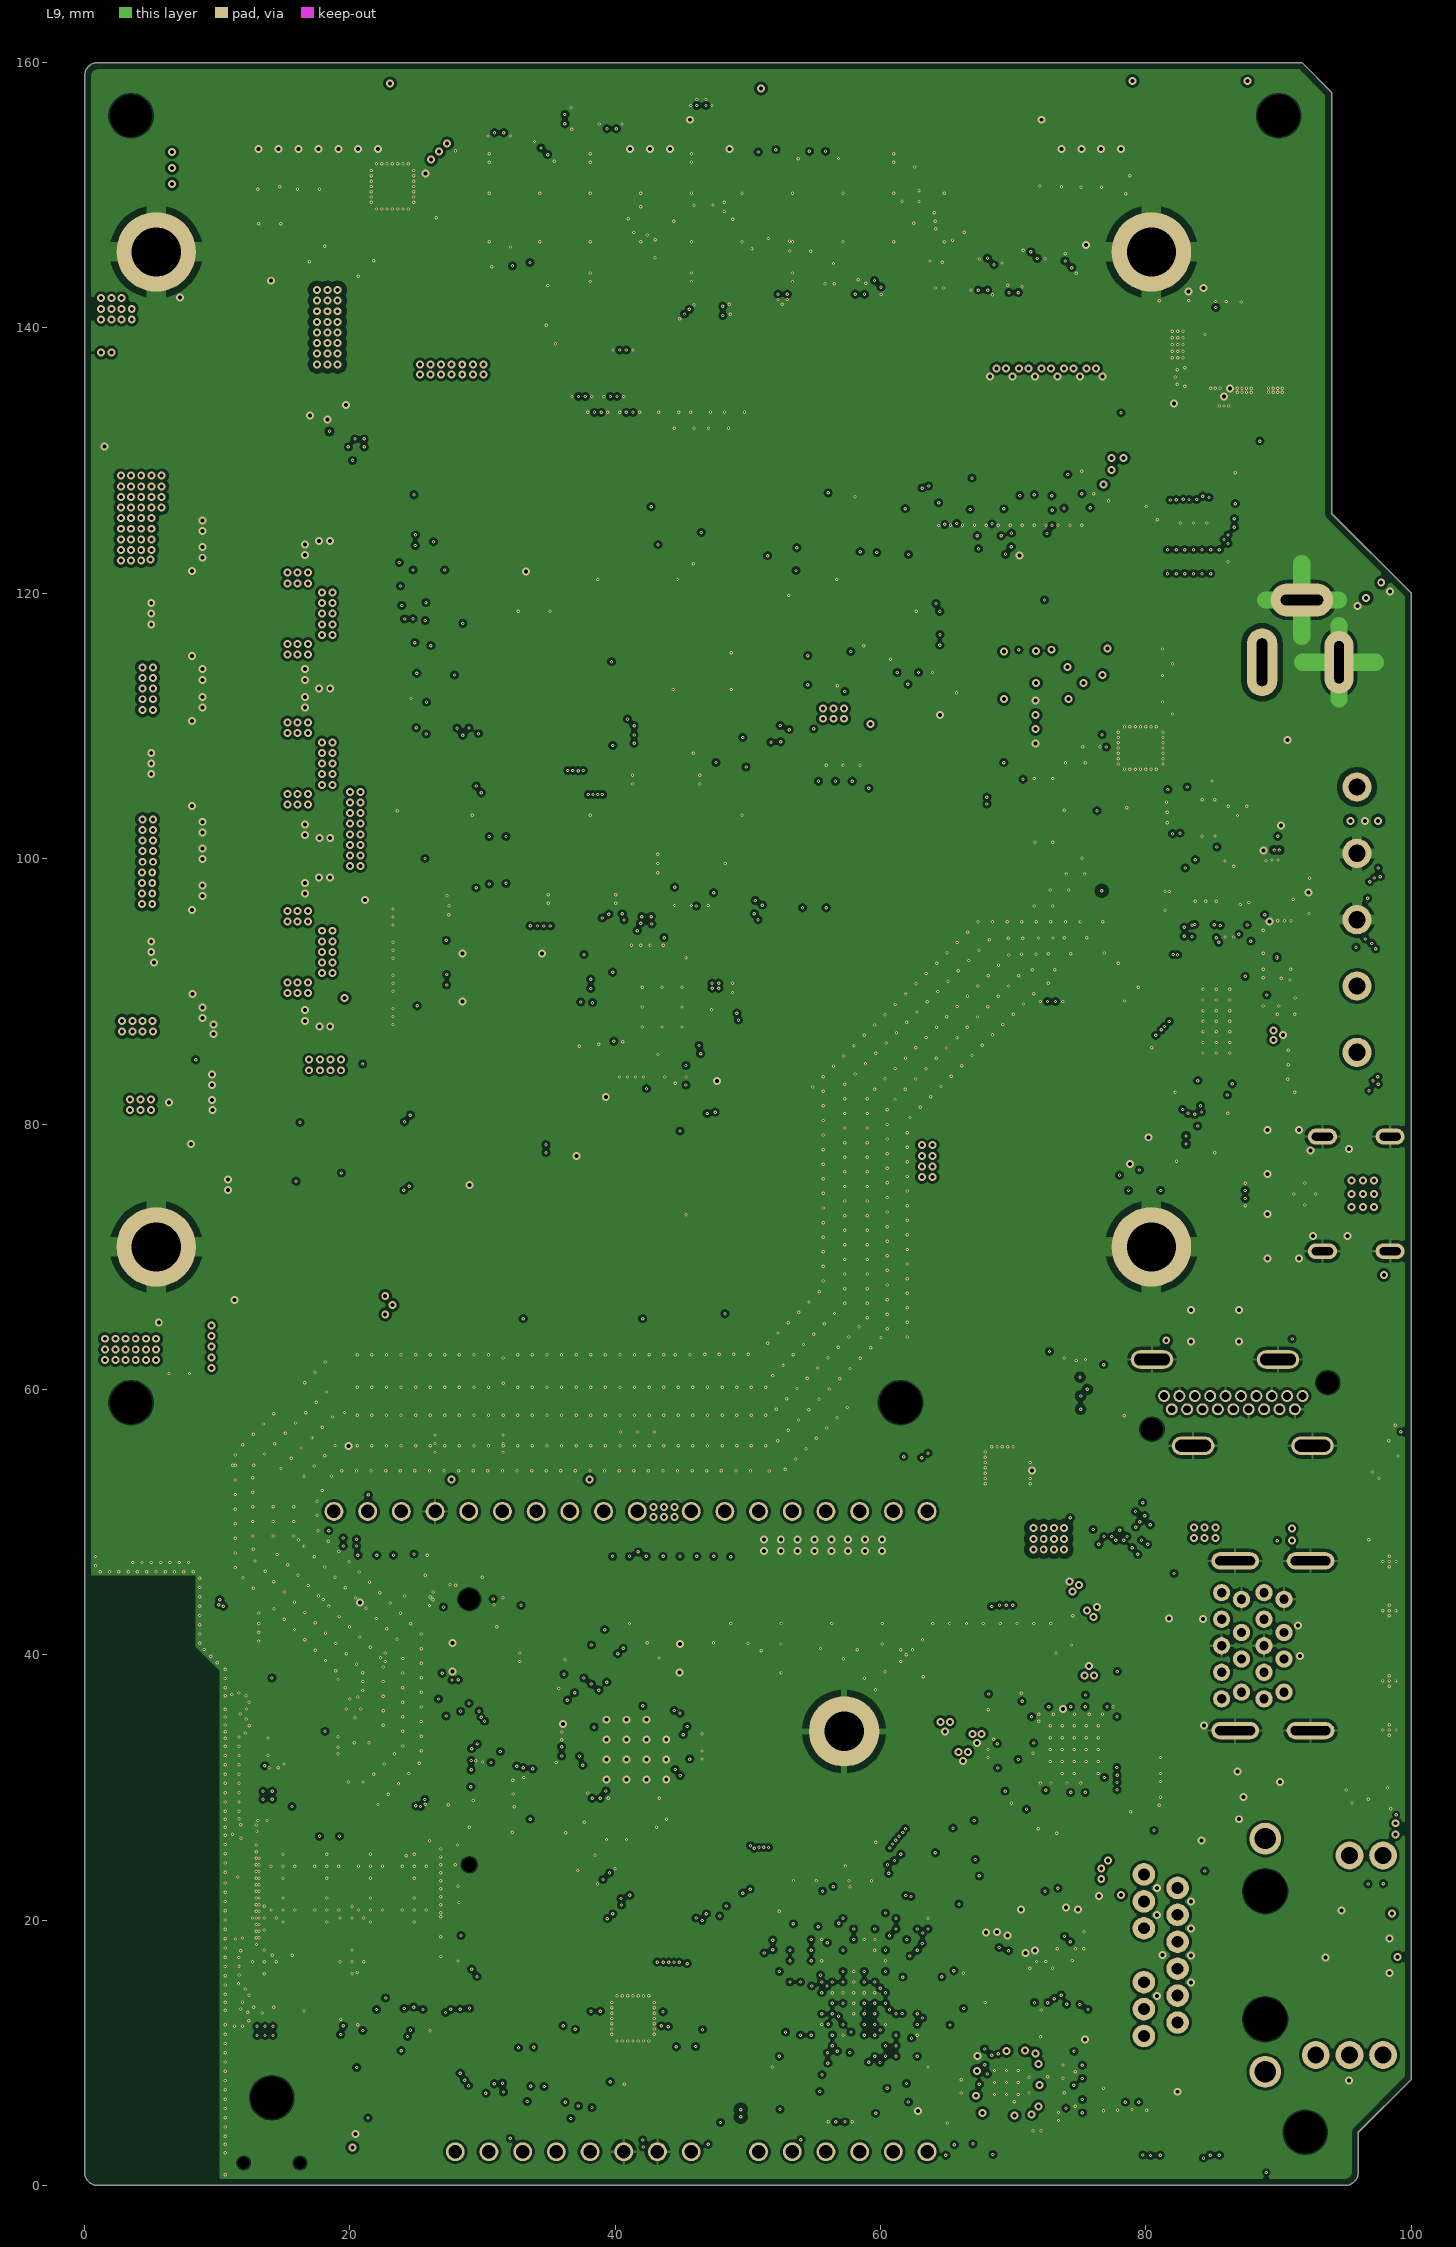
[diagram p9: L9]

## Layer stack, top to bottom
Top Solder: solder mask 0.0254, SM-003, Dk 4
TOP_L1: signal copper 0.0364
Dielectric 6: prepreg 0.0622, S1000HB, Dk 3.73
L2: signal copper 0.0318
Dielectric 4: prepreg 0.0744, S1000HB, Dk 3.73
L3: signal copper 0.0318
Dielectric 2: core 0.2032, S1000HB, Dk 3.73
L4: signal copper 0.0318
Dielectric 1: prepreg 0.3683, S1000H, Dk 3.73
L5: signal copper 0.0318
Dielectric2: core 0.2032, S000HB, Dk 3.73
L6: signal copper 0.0318
Dielectric3: prepreg 0.3683, S1000H, Dk 3.73
L7: signal copper 0.0318
Dielectric 3: core 0.2032, S1000HB, Dk 3.73
L8: signal copper 0.0318
Dielectric 5: prepreg 0.0744, S1000HB, Dk 3.73
L9: signal copper 0.0318
Dielectric 7: prepreg 0.0622, S1000HB, Dk 3.73
BOTTOM_L10: signal copper 0.0364
Bottom Solder: solder mask 0.0254, SM-003, Dk 4

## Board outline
0,1 0,159 cw(c1,159) 1,160 91.749,160 94,157.749 94,126 100,120 100,8 96,4 96,1 cw(c95,1) 95,0 1,0 cw(c1,1)

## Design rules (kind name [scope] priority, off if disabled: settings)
BoardOutlineClearance BoardOutlineClearance_usba [(ObjectKind = 'Pad') And (Component = 'J1')] p1: gap=0.2 ignorepadtopadclearanceinfootprint=FALSE
BoardOutlineClearance BoardOutlineClearance_qwiic [(ObjectKind = 'Pad') And (Component = 'J13')] p2: gap=0.2 ignorepadtopadclearanceinfootprint=FALSE
BoardOutlineClearance BoardOutlineClearance_button [(ObjectKind = 'Pad') And (Component = 'PB2') And (AsMM(PadXSize_AllLayers) = 1.3) And (AsMM(PadYSize_AllLayers) = 0.8)] p3: gap=0.15 ignorepadtopadclearanceinfootprint=FALSE
BoardOutlineClearance Silks [(OnLayer('Top Overlay') OR OnLayer('Bottom Overlay'))] p4: gap=0 ignorepadtopadclearanceinfootprint=FALSE
BoardOutlineClearance [All] p5: gap=0.5 ignorepadtopadclearanceinfootprint=FALSE
Clearance Clearance_7_24V_poly [InNet('7V-24V')] p1: gap=0.24 ignorepadtopadclearanceinfootprint=TRUE except(0.4: Arc-Fill Arc-Poly Arc-Region Track-Fill Track-Poly Track-Region SMDPad-Fill SMDPad-Poly SMDPad-Region THPad-Fill THPad-Poly THPad-Region Via-Fill Via-Poly Via-Region Fill-Fill Fill-Poly Fill-Region Poly-Poly Poly-Region Region-Region)
Clearance Clearance_DC_IN [InNetClass('HIGH_CLEARANCE')] p2: gap=0.24 ignorepadtopadclearanceinfootprint=TRUE
Clearance Clearance_ADV7535BCBZ-RL [WithinRoom('ADV7535BCBZ-RL')] p3: gap=0.084 ignorepadtopadclearanceinfootprint=TRUE except(0.3: Arc-Fill Arc-Poly Arc-Region Track-Fill Track-Poly Track-Region SMDPad-Fill SMDPad-Poly SMDPad-Region THPad-Fill THPad-Poly THPad-Region Via-Fill Via-Poly Via-Region Fill-Fill Fill-Poly Fill-Region Poly-Poly Poly-Region Region-Region)
Clearance CLEARANCE_TMUX646ZECR [WithinRoom('TMUX646ZECR') or   WithinRoom('TMUX646ZECR_1')     OR WithinRoom('TMUX646ZECR_2')] p4: gap=0.076 ignorepadtopadclearanceinfootprint=TRUE except(0.3: Arc-Fill Arc-Poly Arc-Region Track-Fill Track-Poly Track-Region SMDPad-Fill SMDPad-Poly SMDPad-Region THPad-Fill THPad-Poly THPad-Region Via-Fill Via-Poly Via-Region Fill-Fill Fill-Poly Fill-Region Poly-Poly Poly-Region Region-Region)
Clearance CLEARANCE_MIN [All] p5: gap=0.1 ignorepadtopadclearanceinfootprint=FALSE except(0.2: Arc-Fill Arc-Poly Arc-Region Track-Fill Track-Poly Track-Region SMDPad-Fill SMDPad-Poly SMDPad-Region THPad-Fill THPad-Poly THPad-Region Via-Fill Via-Poly Via-Region Fill-Fill Fill-Poly Fill-Region Poly-Poly Poly-Region Region-Region)
ComponentClearance 0201_0201_CAP [HasFootprint('CAP-0201') vs HasFootprint('CAP-0201')] p1: gap=0.254 collisioncheckmode=3 verticalgap=0.254 showdistances=TRUE
ComponentClearance 0201_0201_RES [HasFootprint('RES-0201') vs HasFootprint('RES-0201')] p2: gap=0.254 collisioncheckmode=3 verticalgap=0.254 showdistances=TRUE
ComponentClearance 0201_0201_RES_CAP [HasFootprint('CAP-0201') vs HasFootprint('RES-0201')] p3: gap=0.254 collisioncheckmode=3 verticalgap=0.254 showdistances=TRUE
ComponentClearance 0201_0402_CAP [HasFootprint('CAP-0201') vs HasFootprint('CAP-0402')] p4: gap=0.305 collisioncheckmode=3 verticalgap=0.254 showdistances=FALSE
ComponentClearance 0201_0603 [HasFootprint('CAP-0201') vs HasFootprint('No Footprint')] p5: gap=0.305 collisioncheckmode=3 verticalgap=0.254 showdistances=FALSE
ComponentClearance 0201_0805 [HasFootprint('CAP-0201') vs HasFootprint('CAP-0805')] p6: gap=0.305 collisioncheckmode=3 verticalgap=0.254 showdistances=FALSE
ComponentClearance 0402_0805 [HasFootprint('CAP-0402') vs HasFootprint('CAP-0805')] p7: gap=0.305 collisioncheckmode=3 verticalgap=0.254 showdistances=FALSE
ComponentClearance 0402_0402 [HasFootprint('CAP-0402') vs HasFootprint('CAP-0402')] p8: gap=0.305 collisioncheckmode=3 verticalgap=0.254 showdistances=FALSE
ComponentClearance 0603_0603 [HasFootprint('CAP-0603') vs HasFootprint('CAP-0603')] p9: gap=0.305 collisioncheckmode=3 verticalgap=0.254 showdistances=FALSE
ComponentClearance 0603_0805 [HasFootprint('CAP-0603') vs HasFootprint('CAP-0805')] p10: gap=0.305 collisioncheckmode=3 verticalgap=0.254 showdistances=FALSE
ComponentClearance 0805_0805 [HasFootprint('CAP-0805') vs HasFootprint('CAP-0805')] p11: gap=0.406 collisioncheckmode=3 verticalgap=0.254 showdistances=FALSE
ComponentClearance ComponentClearance_TP [HasFootprint('TP-1.00MM') vs HasFootprint('TP-1.00MM')] p12: gap=0.94 collisioncheckmode=3 verticalgap=0.254 showdistances=FALSE
ComponentClearance [All] p13: gap=0.2 collisioncheckmode=3 verticalgap=0 showdistances=TRUE
DiffPairsRouting DiffPairsRouting_ADV7535BCBZ-RL [WithinRoom('ADV7535BCBZ-RL')] p1: maxlimit=0.254 minlimit=0.084 mostfreqgap=0.166 toplayer_maxgap=0.218 toplayer_prefgap=0.218 toplayer_minwidth=0.084 toplayer_maxwidth=0.086 toplayer_prefwidth=0.086 midlayer4_mingap=0.221 midlayer4_maxgap=0.221 midlayer4_prefgap=0.221 midlayer4_minwidth=0.084 midlayer4_maxwidth=0.084 midlayer4_prefwidth=0.084 midlayer7_mingap=0.221 midlayer7_maxgap=0.221 midlayer7_prefgap=0.221 midlayer7_minwidth=0.084 midlayer7_maxwidth=0.084 midlayer7_prefwidth=0.084 bottomlayer_mingap=0.218 bottomlayer_maxgap=0.218 bottomlayer_prefgap=0.218 bottomlayer_minwidth=0.086 bottomlayer_maxwidth=0.086 bottomlayer_prefwidth=0.086 impedanceprofiledriven=TRUE impedanceprofileid={72B7EF18-E108-4503-8DFF-05138B0E1A69} impedanceprofilevalue=100.000000 maxuncoupledlength=12.7
DiffPairsRouting DIFF_ROUTE_MUX_USBC [InDifferentialPairClass('DIFF_MUX_USBC')] p2: maxlimit=0.254 minlimit=0.127 mostfreqgap=0.127 toplayer_mingap=0.196 toplayer_maxgap=0.196 toplayer_prefgap=0.196 toplayer_minwidth=0.109 toplayer_maxwidth=0.109 toplayer_prefwidth=0.109 midlayer4_mingap=0.201 midlayer4_maxgap=0.201 midlayer4_prefgap=0.201 midlayer4_minwidth=0.104 midlayer4_maxwidth=0.104 midlayer4_prefwidth=0.104 midlayer7_mingap=0.201 midlayer7_maxgap=0.201 midlayer7_prefgap=0.201 midlayer7_minwidth=0.104 midlayer7_maxwidth=0.104 midlayer7_prefwidth=0.104 bottomlayer_mingap=0.196 bottomlayer_maxgap=0.196 bottomlayer_prefgap=0.196 bottomlayer_minwidth=0.109 bottomlayer_maxwidth=0.109 bottomlayer_prefwidth=0.109 impedanceprofiledriven=TRUE impedanceprofileid={E6B00C31-4C8E-439C-824F-D2B2CDC26F9C} impedanceprofilevalue=90.000000 maxuncoupledlength=12.7
DiffPairsRouting DIFF_ROUTE_USB1_DOWN [InDifferentialPairClass('TUSB_USB1')] p3: maxlimit=0.254 minlimit=0.127 mostfreqgap=0.127 toplayer_mingap=0.196 toplayer_maxgap=0.196 toplayer_prefgap=0.196 toplayer_minwidth=0.109 toplayer_maxwidth=0.109 toplayer_prefwidth=0.109 midlayer4_mingap=0.201 midlayer4_maxgap=0.201 midlayer4_prefgap=0.201 midlayer4_minwidth=0.104 midlayer4_maxwidth=0.104 midlayer4_prefwidth=0.104 midlayer7_mingap=0.201 midlayer7_maxgap=0.201 midlayer7_prefgap=0.201 midlayer7_minwidth=0.104 midlayer7_maxwidth=0.104 midlayer7_prefwidth=0.104 bottomlayer_mingap=0.196 bottomlayer_maxgap=0.196 bottomlayer_prefgap=0.196 bottomlayer_minwidth=0.109 bottomlayer_maxwidth=0.109 bottomlayer_prefwidth=0.109 impedanceprofiledriven=TRUE impedanceprofileid={E6B00C31-4C8E-439C-824F-D2B2CDC26F9C} impedanceprofilevalue=90.000000 maxuncoupledlength=12.7
DiffPairsRouting DIFF_ROUTE_USB1_DOWN_CAP [InDifferentialPairClass('TUSB_USB1_CAP')] p4: maxlimit=0.254 minlimit=0.127 mostfreqgap=0.127 toplayer_mingap=0.196 toplayer_maxgap=0.196 toplayer_prefgap=0.196 toplayer_minwidth=0.109 toplayer_maxwidth=0.109 toplayer_prefwidth=0.109 midlayer4_mingap=0.201 midlayer4_maxgap=0.201 midlayer4_prefgap=0.201 midlayer4_minwidth=0.104 midlayer4_maxwidth=0.104 midlayer4_prefwidth=0.104 midlayer7_mingap=0.201 midlayer7_maxgap=0.201 midlayer7_prefgap=0.201 midlayer7_minwidth=0.104 midlayer7_maxwidth=0.104 midlayer7_prefwidth=0.104 bottomlayer_mingap=0.196 bottomlayer_maxgap=0.196 bottomlayer_prefgap=0.196 bottomlayer_minwidth=0.109 bottomlayer_maxwidth=0.109 bottomlayer_prefwidth=0.109 impedanceprofiledriven=TRUE impedanceprofileid={E6B00C31-4C8E-439C-824F-D2B2CDC26F9C} impedanceprofilevalue=90.000000 maxuncoupledlength=12.7
DiffPairsRouting DIFF_ROUTE_USB2_DOWN [InDifferentialPairClass('TUSB_USB2')] p5: maxlimit=0.254 minlimit=0.127 mostfreqgap=0.127 toplayer_mingap=0.196 toplayer_maxgap=0.196 toplayer_prefgap=0.196 toplayer_minwidth=0.109 toplayer_maxwidth=0.109 toplayer_prefwidth=0.109 midlayer4_mingap=0.201 midlayer4_maxgap=0.201 midlayer4_prefgap=0.201 midlayer4_minwidth=0.104 midlayer4_maxwidth=0.104 midlayer4_prefwidth=0.104 midlayer7_mingap=0.201 midlayer7_maxgap=0.201 midlayer7_prefgap=0.201 midlayer7_minwidth=0.104 midlayer7_maxwidth=0.104 midlayer7_prefwidth=0.104 bottomlayer_mingap=0.196 bottomlayer_maxgap=0.196 bottomlayer_prefgap=0.196 bottomlayer_minwidth=0.109 bottomlayer_maxwidth=0.109 bottomlayer_prefwidth=0.109 impedanceprofiledriven=TRUE impedanceprofileid={E6B00C31-4C8E-439C-824F-D2B2CDC26F9C} impedanceprofilevalue=90.000000 maxuncoupledlength=12.7
DiffPairsRouting DIFF_ROUTE_USB2_DOWN_CAP [InDifferentialPairClass('TUSB_USB2_CAP')] p6: maxlimit=0.254 minlimit=0.127 mostfreqgap=0.127 toplayer_mingap=0.196 toplayer_maxgap=0.196 toplayer_prefgap=0.196 toplayer_minwidth=0.109 toplayer_maxwidth=0.109 toplayer_prefwidth=0.109 midlayer4_mingap=0.201 midlayer4_maxgap=0.201 midlayer4_prefgap=0.201 midlayer4_minwidth=0.104 midlayer4_maxwidth=0.104 midlayer4_prefwidth=0.104 midlayer7_mingap=0.201 midlayer7_maxgap=0.201 midlayer7_prefgap=0.201 midlayer7_minwidth=0.104 midlayer7_maxwidth=0.104 midlayer7_prefwidth=0.104 bottomlayer_mingap=0.196 bottomlayer_maxgap=0.196 bottomlayer_prefgap=0.196 bottomlayer_minwidth=0.109 bottomlayer_maxwidth=0.109 bottomlayer_prefwidth=0.109 impedanceprofiledriven=TRUE impedanceprofileid={E6B00C31-4C8E-439C-824F-D2B2CDC26F9C} impedanceprofilevalue=90.000000 maxuncoupledlength=12.7
DiffPairsRouting DIFF_ROUTE_USB3_DOWN [InDifferentialPairClass('TUSB_USB3')] p7: maxlimit=0.254 minlimit=0.127 mostfreqgap=0.127 toplayer_mingap=0.196 toplayer_maxgap=0.196 toplayer_prefgap=0.196 toplayer_minwidth=0.109 toplayer_maxwidth=0.109 toplayer_prefwidth=0.109 midlayer4_mingap=0.201 midlayer4_maxgap=0.201 midlayer4_prefgap=0.201 midlayer4_minwidth=0.104 midlayer4_maxwidth=0.104 midlayer4_prefwidth=0.104 midlayer7_mingap=0.201 midlayer7_maxgap=0.201 midlayer7_prefgap=0.201 midlayer7_minwidth=0.104 midlayer7_maxwidth=0.104 midlayer7_prefwidth=0.104 bottomlayer_mingap=0.196 bottomlayer_maxgap=0.196 bottomlayer_prefgap=0.196 bottomlayer_minwidth=0.109 bottomlayer_maxwidth=0.109 bottomlayer_prefwidth=0.109 impedanceprofiledriven=TRUE impedanceprofileid={E6B00C31-4C8E-439C-824F-D2B2CDC26F9C} impedanceprofilevalue=90.000000 maxuncoupledlength=12.7
DiffPairsRouting DIFF_ROUTE_USB3_DOWN_CAP [InDifferentialPairClass('TUSB_USB3_CAP')] p8: maxlimit=0.254 minlimit=0.127 mostfreqgap=0.127 toplayer_mingap=0.196 toplayer_maxgap=0.196 toplayer_prefgap=0.196 toplayer_minwidth=0.109 toplayer_maxwidth=0.109 toplayer_prefwidth=0.109 midlayer4_mingap=0.201 midlayer4_maxgap=0.201 midlayer4_prefgap=0.201 midlayer4_minwidth=0.104 midlayer4_maxwidth=0.104 midlayer4_prefwidth=0.104 midlayer7_mingap=0.201 midlayer7_maxgap=0.201 midlayer7_prefgap=0.201 midlayer7_minwidth=0.104 midlayer7_maxwidth=0.104 midlayer7_prefwidth=0.104 bottomlayer_mingap=0.196 bottomlayer_maxgap=0.196 bottomlayer_prefgap=0.196 bottomlayer_minwidth=0.109 bottomlayer_maxwidth=0.109 bottomlayer_prefwidth=0.109 impedanceprofiledriven=TRUE impedanceprofileid={E6B00C31-4C8E-439C-824F-D2B2CDC26F9C} impedanceprofilevalue=90.000000 maxuncoupledlength=12.7
DiffPairsRouting DIFF_ROUTE_USB4_DOWN [InDifferentialPairClass('TUSB_USB4')] p9: maxlimit=0.254 minlimit=0.127 mostfreqgap=0.127 toplayer_mingap=0.196 toplayer_maxgap=0.196 toplayer_prefgap=0.196 toplayer_minwidth=0.109 toplayer_maxwidth=0.109 toplayer_prefwidth=0.109 midlayer4_mingap=0.201 midlayer4_maxgap=0.201 midlayer4_prefgap=0.201 midlayer4_minwidth=0.104 midlayer4_maxwidth=0.104 midlayer4_prefwidth=0.104 midlayer7_mingap=0.201 midlayer7_maxgap=0.201 midlayer7_prefgap=0.201 midlayer7_minwidth=0.104 midlayer7_maxwidth=0.104 midlayer7_prefwidth=0.104 bottomlayer_mingap=0.196 bottomlayer_maxgap=0.196 bottomlayer_prefgap=0.196 bottomlayer_minwidth=0.109 bottomlayer_maxwidth=0.109 bottomlayer_prefwidth=0.109 impedanceprofiledriven=TRUE impedanceprofileid={E6B00C31-4C8E-439C-824F-D2B2CDC26F9C} impedanceprofilevalue=90.000000 maxuncoupledlength=12.7
DiffPairsRouting DIFF_ROUTE_USB4_DOWN_CAP [InDifferentialPairClass('TUSB_USB4_CAP')] p10: maxlimit=0.254 minlimit=0.127 mostfreqgap=0.127 toplayer_mingap=0.196 toplayer_maxgap=0.196 toplayer_prefgap=0.196 toplayer_minwidth=0.109 toplayer_maxwidth=0.109 toplayer_prefwidth=0.109 midlayer4_mingap=0.201 midlayer4_maxgap=0.201 midlayer4_prefgap=0.201 midlayer4_minwidth=0.104 midlayer4_maxwidth=0.104 midlayer4_prefwidth=0.104 midlayer7_mingap=0.201 midlayer7_maxgap=0.201 midlayer7_prefgap=0.201 midlayer7_minwidth=0.104 midlayer7_maxwidth=0.104 midlayer7_prefwidth=0.104 bottomlayer_mingap=0.196 bottomlayer_maxgap=0.196 bottomlayer_prefgap=0.196 bottomlayer_minwidth=0.109 bottomlayer_maxwidth=0.109 bottomlayer_prefwidth=0.109 impedanceprofiledriven=TRUE impedanceprofileid={E6B00C31-4C8E-439C-824F-D2B2CDC26F9C} impedanceprofilevalue=90.000000 maxuncoupledlength=12.7
DiffPairsRouting DIFF_ROUTE_ETHPHY [InDifferentialPairClass('DIFF_ETHPHY')] p11: maxlimit=0.254 minlimit=0.127 mostfreqgap=0.127 toplayer_mingap=0.218 toplayer_maxgap=0.218 toplayer_prefgap=0.218 toplayer_minwidth=0.086 toplayer_maxwidth=0.086 toplayer_prefwidth=0.086 midlayer4_mingap=0.221 midlayer4_maxgap=0.221 midlayer4_prefgap=0.221 midlayer4_minwidth=0.084 midlayer4_maxwidth=0.084 midlayer4_prefwidth=0.084 midlayer7_mingap=0.221 midlayer7_maxgap=0.221 midlayer7_prefgap=0.221 midlayer7_minwidth=0.084 midlayer7_maxwidth=0.084 midlayer7_prefwidth=0.084 bottomlayer_mingap=0.218 bottomlayer_maxgap=0.218 bottomlayer_prefgap=0.218 bottomlayer_minwidth=0.086 bottomlayer_maxwidth=0.086 bottomlayer_prefwidth=0.086 impedanceprofiledriven=TRUE impedanceprofileid={72B7EF18-E108-4503-8DFF-05138B0E1A69} impedanceprofilevalue=100.000000 maxuncoupledlength=12.7
DiffPairsRouting DIFF_ROUTE_MUXCAPS_USBC [InDifferentialPairClass('DIFF_MUXCAPS_USBC')] p12: maxlimit=0.254 minlimit=0.127 mostfreqgap=0.127 toplayer_mingap=0.196 toplayer_maxgap=0.196 toplayer_prefgap=0.196 toplayer_minwidth=0.109 toplayer_maxwidth=0.109 toplayer_prefwidth=0.109 midlayer4_mingap=0.201 midlayer4_maxgap=0.201 midlayer4_prefgap=0.201 midlayer4_minwidth=0.104 midlayer4_maxwidth=0.104 midlayer4_prefwidth=0.104 midlayer7_mingap=0.201 midlayer7_maxgap=0.201 midlayer7_prefgap=0.201 midlayer7_minwidth=0.104 midlayer7_maxwidth=0.104 midlayer7_prefwidth=0.104 bottomlayer_mingap=0.196 bottomlayer_maxgap=0.196 bottomlayer_prefgap=0.196 bottomlayer_minwidth=0.109 bottomlayer_maxwidth=0.109 bottomlayer_prefwidth=0.109 impedanceprofiledriven=TRUE impedanceprofileid={E6B00C31-4C8E-439C-824F-D2B2CDC26F9C} impedanceprofilevalue=90.000000 maxuncoupledlength=12.7
DiffPairsRouting DIFF_ROUTE_MD_USB0 [InDifferentialPairClass('DIFF_MD_USB0')] p13: maxlimit=0.254 minlimit=0.127 mostfreqgap=0.127 toplayer_mingap=0.196 toplayer_maxgap=0.196 toplayer_prefgap=0.196 toplayer_minwidth=0.109 toplayer_maxwidth=0.109 toplayer_prefwidth=0.109 midlayer4_mingap=0.201 midlayer4_maxgap=0.201 midlayer4_prefgap=0.201 midlayer4_minwidth=0.104 midlayer4_maxwidth=0.104 midlayer4_prefwidth=0.104 midlayer7_mingap=0.201 midlayer7_maxgap=0.201 midlayer7_prefgap=0.201 midlayer7_minwidth=0.104 midlayer7_maxwidth=0.104 midlayer7_prefwidth=0.104 bottomlayer_mingap=0.196 bottomlayer_maxgap=0.196 bottomlayer_prefgap=0.196 bottomlayer_minwidth=0.109 bottomlayer_maxwidth=0.109 bottomlayer_prefwidth=0.109 impedanceprofiledriven=TRUE impedanceprofileid={E6B00C31-4C8E-439C-824F-D2B2CDC26F9C} impedanceprofilevalue=90.000000 maxuncoupledlength=12.7
DiffPairsRouting DIFF_ROUTE_MD_USB1 [InDifferentialPairClass('DIFF_MD_USB1')] p14: maxlimit=0.254 minlimit=0.127 mostfreqgap=0.127 toplayer_mingap=0.196 toplayer_maxgap=0.196 toplayer_prefgap=0.196 toplayer_minwidth=0.109 toplayer_maxwidth=0.109 toplayer_prefwidth=0.109 midlayer4_mingap=0.201 midlayer4_maxgap=0.201 midlayer4_prefgap=0.201 midlayer4_minwidth=0.104 midlayer4_maxwidth=0.104 midlayer4_prefwidth=0.104 midlayer7_mingap=0.201 midlayer7_maxgap=0.201 midlayer7_prefgap=0.201 midlayer7_minwidth=0.104 midlayer7_maxwidth=0.104 midlayer7_prefwidth=0.104 bottomlayer_mingap=0.196 bottomlayer_maxgap=0.196 bottomlayer_prefgap=0.196 bottomlayer_minwidth=0.109 bottomlayer_maxwidth=0.109 bottomlayer_prefwidth=0.109 impedanceprofiledriven=TRUE impedanceprofileid={E6B00C31-4C8E-439C-824F-D2B2CDC26F9C} impedanceprofilevalue=90.000000 maxuncoupledlength=12.7
DiffPairsRouting DIFF_ROUTE_USB_MODULE [InDifferentialPairClass('DIFF_USB_MODULE')] p15: maxlimit=0.254 minlimit=0.127 mostfreqgap=0.127 toplayer_mingap=0.196 toplayer_maxgap=0.196 toplayer_prefgap=0.196 toplayer_minwidth=0.109 toplayer_maxwidth=0.109 toplayer_prefwidth=0.109 midlayer4_mingap=0.201 midlayer4_maxgap=0.201 midlayer4_prefgap=0.201 midlayer4_minwidth=0.104 midlayer4_maxwidth=0.104 midlayer4_prefwidth=0.104 midlayer7_mingap=0.201 midlayer7_maxgap=0.201 midlayer7_prefgap=0.201 midlayer7_minwidth=0.104 midlayer7_maxwidth=0.104 midlayer7_prefwidth=0.104 bottomlayer_mingap=0.196 bottomlayer_maxgap=0.196 bottomlayer_prefgap=0.196 bottomlayer_minwidth=0.109 bottomlayer_maxwidth=0.109 bottomlayer_prefwidth=0.109 impedanceprofiledriven=TRUE impedanceprofileid={E6B00C31-4C8E-439C-824F-D2B2CDC26F9C} impedanceprofilevalue=90.000000 maxuncoupledlength=12.7
DiffPairsRouting DIFF_ROUTE_SGMII [InDifferentialPairClass('DIFF_MD_SGMII')] p16: maxlimit=0.254 minlimit=0.127 mostfreqgap=0.127 toplayer_mingap=0.196 toplayer_maxgap=0.196 toplayer_prefgap=0.196 toplayer_minwidth=0.109 toplayer_maxwidth=0.109 toplayer_prefwidth=0.109 midlayer4_mingap=0.201 midlayer4_maxgap=0.201 midlayer4_prefgap=0.201 midlayer4_minwidth=0.104 midlayer4_maxwidth=0.104 midlayer4_prefwidth=0.104 midlayer7_mingap=0.201 midlayer7_maxgap=0.201 midlayer7_prefgap=0.201 midlayer7_minwidth=0.104 midlayer7_maxwidth=0.104 midlayer7_prefwidth=0.104 bottomlayer_mingap=0.196 bottomlayer_maxgap=0.196 bottomlayer_prefgap=0.196 bottomlayer_minwidth=0.109 bottomlayer_maxwidth=0.109 bottomlayer_prefwidth=0.109 impedanceprofiledriven=TRUE impedanceprofileid={E6B00C31-4C8E-439C-824F-D2B2CDC26F9C} impedanceprofilevalue=90.000000 maxuncoupledlength=12.7
DiffPairsRouting DIFF_ROUTE_MD_PCIE0 [InDifferentialPairClass('DIFF_MD_PCIE0')] p17: maxlimit=0.254 minlimit=0.127 mostfreqgap=0.127 toplayer_mingap=0.183 toplayer_maxgap=0.183 toplayer_prefgap=0.183 toplayer_minwidth=0.122 toplayer_maxwidth=0.122 toplayer_prefwidth=0.122 midlayer4_mingap=0.188 midlayer4_maxgap=0.188 midlayer4_prefgap=0.188 midlayer4_minwidth=0.117 midlayer4_maxwidth=0.117 midlayer4_prefwidth=0.117 midlayer7_mingap=0.188 midlayer7_maxgap=0.188 midlayer7_prefgap=0.188 midlayer7_minwidth=0.117 midlayer7_maxwidth=0.117 midlayer7_prefwidth=0.117 bottomlayer_mingap=0.183 bottomlayer_maxgap=0.183 bottomlayer_prefgap=0.183 bottomlayer_minwidth=0.122 bottomlayer_maxwidth=0.122 bottomlayer_prefwidth=0.122 impedanceprofiledriven=TRUE impedanceprofileid={49CC0F8D-1F3C-4D86-8ACD-DA3CEB1E83F8} impedanceprofilevalue=85.000000 maxuncoupledlength=12.7
DiffPairsRouting DIFF_ROUTE_MD_PCIE1 [InDifferentialPairClass('DIFF_MD_PCIE1')] p18: maxlimit=0.254 minlimit=0.127 mostfreqgap=0.127 toplayer_mingap=0.183 toplayer_maxgap=0.183 toplayer_prefgap=0.183 toplayer_minwidth=0.122 toplayer_maxwidth=0.122 toplayer_prefwidth=0.122 midlayer4_mingap=0.188 midlayer4_maxgap=0.188 midlayer4_prefgap=0.188 midlayer4_minwidth=0.117 midlayer4_maxwidth=0.117 midlayer4_prefwidth=0.117 midlayer7_mingap=0.188 midlayer7_maxgap=0.188 midlayer7_prefgap=0.188 midlayer7_minwidth=0.117 midlayer7_maxwidth=0.117 midlayer7_prefwidth=0.117 bottomlayer_mingap=0.183 bottomlayer_maxgap=0.183 bottomlayer_prefgap=0.183 bottomlayer_minwidth=0.122 bottomlayer_maxwidth=0.122 bottomlayer_prefwidth=0.122 impedanceprofiledriven=TRUE impedanceprofileid={49CC0F8D-1F3C-4D86-8ACD-DA3CEB1E83F8} impedanceprofilevalue=85.000000 maxuncoupledlength=12.7
DiffPairsRouting DIFF_ROUTE_PCIE_PET [InDifferentialPairClass('DIFF_PCIE_PET')] p19: maxlimit=0.254 minlimit=0.127 mostfreqgap=0.127 toplayer_mingap=0.183 toplayer_maxgap=0.183 toplayer_prefgap=0.183 toplayer_minwidth=0.122 toplayer_maxwidth=0.122 toplayer_prefwidth=0.122 midlayer4_mingap=0.188 midlayer4_maxgap=0.188 midlayer4_prefgap=0.188 midlayer4_minwidth=0.117 midlayer4_maxwidth=0.117 midlayer4_prefwidth=0.117 midlayer7_mingap=0.188 midlayer7_maxgap=0.188 midlayer7_prefgap=0.188 midlayer7_minwidth=0.117 midlayer7_maxwidth=0.117 midlayer7_prefwidth=0.117 bottomlayer_mingap=0.183 bottomlayer_maxgap=0.183 bottomlayer_prefgap=0.183 bottomlayer_minwidth=0.122 bottomlayer_maxwidth=0.122 bottomlayer_prefwidth=0.122 impedanceprofiledriven=TRUE impedanceprofileid={49CC0F8D-1F3C-4D86-8ACD-DA3CEB1E83F8} impedanceprofilevalue=85.000000 maxuncoupledlength=12.7
DiffPairsRouting DIFF_ROUTE_PCIE_USB_CAPS [InDifferentialPairClass('PCIE_USB_CAPS')] p20: maxlimit=0.254 minlimit=0.127 mostfreqgap=0.127 toplayer_mingap=0.183 toplayer_maxgap=0.183 toplayer_prefgap=0.183 toplayer_minwidth=0.122 toplayer_maxwidth=0.122 toplayer_prefwidth=0.122 midlayer4_mingap=0.188 midlayer4_maxgap=0.188 midlayer4_prefgap=0.188 midlayer4_minwidth=0.117 midlayer4_maxwidth=0.117 midlayer4_prefwidth=0.117 midlayer7_mingap=0.188 midlayer7_maxgap=0.188 midlayer7_prefgap=0.188 midlayer7_minwidth=0.117 midlayer7_maxwidth=0.117 midlayer7_prefwidth=0.117 bottomlayer_mingap=0.183 bottomlayer_maxgap=0.183 bottomlayer_prefgap=0.183 bottomlayer_minwidth=0.122 bottomlayer_maxwidth=0.122 bottomlayer_prefwidth=0.122 impedanceprofiledriven=TRUE impedanceprofileid={49CC0F8D-1F3C-4D86-8ACD-DA3CEB1E83F8} impedanceprofilevalue=85.000000 maxuncoupledlength=12.7
DiffPairsRouting DIFF_ROUTE_PCIE1_DOWN [InDifferentialPairClass('DIFF_PCIE_DOWN1')] p21: maxlimit=0.254 minlimit=0.127 mostfreqgap=0.127 toplayer_mingap=0.183 toplayer_maxgap=0.183 toplayer_prefgap=0.183 toplayer_minwidth=0.122 toplayer_maxwidth=0.122 toplayer_prefwidth=0.122 midlayer4_mingap=0.188 midlayer4_maxgap=0.188 midlayer4_prefgap=0.188 midlayer4_minwidth=0.117 midlayer4_maxwidth=0.117 midlayer4_prefwidth=0.117 midlayer7_mingap=0.188 midlayer7_maxgap=0.188 midlayer7_prefgap=0.188 midlayer7_minwidth=0.117 midlayer7_maxwidth=0.117 midlayer7_prefwidth=0.117 bottomlayer_mingap=0.183 bottomlayer_maxgap=0.183 bottomlayer_prefgap=0.183 bottomlayer_minwidth=0.122 bottomlayer_maxwidth=0.122 bottomlayer_prefwidth=0.122 impedanceprofiledriven=TRUE impedanceprofileid={49CC0F8D-1F3C-4D86-8ACD-DA3CEB1E83F8} impedanceprofilevalue=85.000000 maxuncoupledlength=12.7
DiffPairsRouting DIFF_ROUTE_PCIE2_DOWN [InDifferentialPairClass('DIFF_PCIE_DOWN2')] p22: maxlimit=0.254 minlimit=0.127 mostfreqgap=0.127 toplayer_mingap=0.183 toplayer_maxgap=0.183 toplayer_prefgap=0.183 toplayer_minwidth=0.122 toplayer_maxwidth=0.122 toplayer_prefwidth=0.122 midlayer4_mingap=0.188 midlayer4_maxgap=0.188 midlayer4_prefgap=0.188 midlayer4_minwidth=0.117 midlayer4_maxwidth=0.117 midlayer4_prefwidth=0.117 midlayer7_mingap=0.188 midlayer7_maxgap=0.188 midlayer7_prefgap=0.188 midlayer7_minwidth=0.117 midlayer7_maxwidth=0.117 midlayer7_prefwidth=0.117 bottomlayer_mingap=0.183 bottomlayer_maxgap=0.183 bottomlayer_prefgap=0.183 bottomlayer_minwidth=0.122 bottomlayer_maxwidth=0.122 bottomlayer_prefwidth=0.122 impedanceprofiledriven=TRUE impedanceprofileid={49CC0F8D-1F3C-4D86-8ACD-DA3CEB1E83F8} impedanceprofilevalue=85.000000 maxuncoupledlength=12.7
DiffPairsRouting DIFF_ROUTE_EDP [InDifferentialPairClass('DIFF_MD_EDP')] p23: maxlimit=0.254 minlimit=0.127 mostfreqgap=0.127 toplayer_mingap=0.196 toplayer_maxgap=0.196 toplayer_prefgap=0.196 toplayer_minwidth=0.109 toplayer_maxwidth=0.109 toplayer_prefwidth=0.109 midlayer4_mingap=0.201 midlayer4_maxgap=0.201 midlayer4_prefgap=0.201 midlayer4_minwidth=0.104 midlayer4_maxwidth=0.104 midlayer4_prefwidth=0.104 midlayer7_mingap=0.201 midlayer7_maxgap=0.201 midlayer7_prefgap=0.201 midlayer7_minwidth=0.104 midlayer7_maxwidth=0.104 midlayer7_prefwidth=0.104 bottomlayer_mingap=0.196 bottomlayer_maxgap=0.196 bottomlayer_prefgap=0.196 bottomlayer_minwidth=0.109 bottomlayer_maxwidth=0.109 bottomlayer_prefwidth=0.109 impedanceprofiledriven=TRUE impedanceprofileid={E6B00C31-4C8E-439C-824F-D2B2CDC26F9C} impedanceprofilevalue=90.000000 maxuncoupledlength=12.7
DiffPairsRouting DIFF_ROUTE_HDMI [InDifferentialPairClass('DIFF_HDMI')] p24: maxlimit=0.254 minlimit=0.127 mostfreqgap=0.127 toplayer_mingap=0.218 toplayer_maxgap=0.218 toplayer_prefgap=0.218 toplayer_minwidth=0.086 toplayer_maxwidth=0.086 toplayer_prefwidth=0.086 midlayer4_mingap=0.221 midlayer4_maxgap=0.221 midlayer4_prefgap=0.221 midlayer4_minwidth=0.084 midlayer4_maxwidth=0.084 midlayer4_prefwidth=0.084 midlayer7_mingap=0.221 midlayer7_maxgap=0.221 midlayer7_prefgap=0.221 midlayer7_minwidth=0.084 midlayer7_maxwidth=0.084 midlayer7_prefwidth=0.084 bottomlayer_mingap=0.218 bottomlayer_maxgap=0.218 bottomlayer_prefgap=0.218 bottomlayer_minwidth=0.086 bottomlayer_maxwidth=0.086 bottomlayer_prefwidth=0.086 impedanceprofiledriven=TRUE impedanceprofileid={72B7EF18-E108-4503-8DFF-05138B0E1A69} impedanceprofilevalue=100.000000 maxuncoupledlength=12.7
DiffPairsRouting DIFF_ROUTE_MD_CSI0 [InDifferentialPairClass('DIFF_MD_CSI0')] p25: maxlimit=0.254 minlimit=0.127 mostfreqgap=0.127 toplayer_mingap=0.196 toplayer_maxgap=0.196 toplayer_prefgap=0.196 toplayer_minwidth=0.109 toplayer_maxwidth=0.109 toplayer_prefwidth=0.109 midlayer4_mingap=0.201 midlayer4_maxgap=0.201 midlayer4_prefgap=0.201 midlayer4_minwidth=0.104 midlayer4_maxwidth=0.104 midlayer4_prefwidth=0.104 midlayer7_mingap=0.201 midlayer7_maxgap=0.201 midlayer7_prefgap=0.201 midlayer7_minwidth=0.104 midlayer7_maxwidth=0.104 midlayer7_prefwidth=0.104 bottomlayer_mingap=0.196 bottomlayer_maxgap=0.196 bottomlayer_prefgap=0.196 bottomlayer_minwidth=0.109 bottomlayer_maxwidth=0.109 bottomlayer_prefwidth=0.109 impedanceprofiledriven=TRUE impedanceprofileid={E6B00C31-4C8E-439C-824F-D2B2CDC26F9C} impedanceprofilevalue=90.000000 maxuncoupledlength=12.7
DiffPairsRouting DIFF_ROUTE_MD_CSI1 [InDifferentialPairClass('DIFF_MD_CSI1')] p26: maxlimit=0.254 minlimit=0.127 mostfreqgap=0.127 toplayer_mingap=0.196 toplayer_maxgap=0.196 toplayer_prefgap=0.196 toplayer_minwidth=0.109 toplayer_maxwidth=0.109 toplayer_prefwidth=0.109 midlayer4_mingap=0.201 midlayer4_maxgap=0.201 midlayer4_prefgap=0.201 midlayer4_minwidth=0.104 midlayer4_maxwidth=0.104 midlayer4_prefwidth=0.104 midlayer7_mingap=0.201 midlayer7_maxgap=0.201 midlayer7_prefgap=0.201 midlayer7_minwidth=0.104 midlayer7_maxwidth=0.104 midlayer7_prefwidth=0.104 bottomlayer_mingap=0.196 bottomlayer_maxgap=0.196 bottomlayer_prefgap=0.196 bottomlayer_minwidth=0.109 bottomlayer_maxwidth=0.109 bottomlayer_prefwidth=0.109 impedanceprofiledriven=TRUE impedanceprofileid={E6B00C31-4C8E-439C-824F-D2B2CDC26F9C} impedanceprofilevalue=90.000000 maxuncoupledlength=12.7
DiffPairsRouting DIFF_ROUTE_MD_CSI2 [InDifferentialPairClass('DIFF_MD_CSI2')] p27: maxlimit=0.254 minlimit=0.127 mostfreqgap=0.127 toplayer_mingap=0.196 toplayer_maxgap=0.196 toplayer_prefgap=0.196 toplayer_minwidth=0.109 toplayer_maxwidth=0.109 toplayer_prefwidth=0.109 midlayer4_mingap=0.201 midlayer4_maxgap=0.201 midlayer4_prefgap=0.201 midlayer4_minwidth=0.104 midlayer4_maxwidth=0.104 midlayer4_prefwidth=0.104 midlayer7_mingap=0.201 midlayer7_maxgap=0.201 midlayer7_prefgap=0.201 midlayer7_minwidth=0.104 midlayer7_maxwidth=0.104 midlayer7_prefwidth=0.104 bottomlayer_mingap=0.196 bottomlayer_maxgap=0.196 bottomlayer_prefgap=0.196 bottomlayer_minwidth=0.109 bottomlayer_maxwidth=0.109 bottomlayer_prefwidth=0.109 impedanceprofiledriven=TRUE impedanceprofileid={E6B00C31-4C8E-439C-824F-D2B2CDC26F9C} impedanceprofilevalue=90.000000 maxuncoupledlength=12.7
DiffPairsRouting DIFF_ROUTE_MD_DSI0 [InDifferentialPairClass('DIFF_MD_DSI0')] p28: maxlimit=0.254 minlimit=0.127 mostfreqgap=0.127 toplayer_mingap=0.196 toplayer_maxgap=0.196 toplayer_prefgap=0.196 toplayer_minwidth=0.109 toplayer_maxwidth=0.109 toplayer_prefwidth=0.109 midlayer4_mingap=0.201 midlayer4_maxgap=0.201 midlayer4_prefgap=0.201 midlayer4_minwidth=0.104 midlayer4_maxwidth=0.104 midlayer4_prefwidth=0.104 midlayer7_mingap=0.201 midlayer7_maxgap=0.201 midlayer7_prefgap=0.201 midlayer7_minwidth=0.104 midlayer7_maxwidth=0.104 midlayer7_prefwidth=0.104 bottomlayer_mingap=0.196 bottomlayer_maxgap=0.196 bottomlayer_prefgap=0.196 bottomlayer_minwidth=0.109 bottomlayer_maxwidth=0.109 bottomlayer_prefwidth=0.109 impedanceprofiledriven=TRUE impedanceprofileid={E6B00C31-4C8E-439C-824F-D2B2CDC26F9C} impedanceprofilevalue=90.000000 maxuncoupledlength=12.7
DiffPairsRouting DIFF_ROUTE_MUX0_OUTA [InDifferentialPairClass('DIFF_MUX0_OUTA')] p29: maxlimit=0.254 minlimit=0.127 mostfreqgap=0.127 toplayer_mingap=0.196 toplayer_maxgap=0.196 toplayer_prefgap=0.196 toplayer_minwidth=0.109 toplayer_maxwidth=0.109 toplayer_prefwidth=0.109 midlayer4_mingap=0.201 midlayer4_maxgap=0.201 midlayer4_prefgap=0.201 midlayer4_minwidth=0.104 midlayer4_maxwidth=0.104 midlayer4_prefwidth=0.104 midlayer7_mingap=0.201 midlayer7_maxgap=0.201 midlayer7_prefgap=0.201 midlayer7_minwidth=0.104 midlayer7_maxwidth=0.104 midlayer7_prefwidth=0.104 bottomlayer_mingap=0.196 bottomlayer_maxgap=0.196 bottomlayer_prefgap=0.196 bottomlayer_minwidth=0.109 bottomlayer_maxwidth=0.109 bottomlayer_prefwidth=0.109 impedanceprofiledriven=TRUE impedanceprofileid={E6B00C31-4C8E-439C-824F-D2B2CDC26F9C} impedanceprofilevalue=90.000000 maxuncoupledlength=12.7
DiffPairsRouting DIFF_ROUTE_MUX0_OUTB [InDifferentialPairClass('DIFF_MUX0_OUTB')] p30: maxlimit=0.254 minlimit=0.127 mostfreqgap=0.127 toplayer_mingap=0.196 toplayer_maxgap=0.196 toplayer_prefgap=0.196 toplayer_minwidth=0.109 toplayer_maxwidth=0.109 toplayer_prefwidth=0.109 midlayer4_mingap=0.201 midlayer4_maxgap=0.201 midlayer4_prefgap=0.201 midlayer4_minwidth=0.104 midlayer4_maxwidth=0.104 midlayer4_prefwidth=0.104 midlayer7_mingap=0.201 midlayer7_maxgap=0.201 midlayer7_prefgap=0.201 midlayer7_minwidth=0.104 midlayer7_maxwidth=0.104 midlayer7_prefwidth=0.104 bottomlayer_mingap=0.196 bottomlayer_maxgap=0.196 bottomlayer_prefgap=0.196 bottomlayer_minwidth=0.109 bottomlayer_maxwidth=0.109 bottomlayer_prefwidth=0.109 impedanceprofiledriven=TRUE impedanceprofileid={E6B00C31-4C8E-439C-824F-D2B2CDC26F9C} impedanceprofilevalue=90.000000 maxuncoupledlength=12.7
DiffPairsRouting DIFF_ROUTE_MUX1_OUTA [InDifferentialPairClass('DIFF_MUX1_OUTA')] p31: maxlimit=0.254 minlimit=0.127 mostfreqgap=0.127 toplayer_mingap=0.196 toplayer_maxgap=0.196 toplayer_prefgap=0.196 toplayer_minwidth=0.109 toplayer_maxwidth=0.109 toplayer_prefwidth=0.109 midlayer4_mingap=0.201 midlayer4_maxgap=0.201 midlayer4_prefgap=0.201 midlayer4_minwidth=0.104 midlayer4_maxwidth=0.104 midlayer4_prefwidth=0.104 midlayer7_mingap=0.201 midlayer7_maxgap=0.201 midlayer7_prefgap=0.201 midlayer7_minwidth=0.104 midlayer7_maxwidth=0.104 midlayer7_prefwidth=0.104 bottomlayer_mingap=0.196 bottomlayer_maxgap=0.196 bottomlayer_prefgap=0.196 bottomlayer_minwidth=0.109 bottomlayer_maxwidth=0.109 bottomlayer_prefwidth=0.109 impedanceprofiledriven=TRUE impedanceprofileid={E6B00C31-4C8E-439C-824F-D2B2CDC26F9C} impedanceprofilevalue=90.000000 maxuncoupledlength=12.7
DiffPairsRouting DIFF_ROUTE_MUX1_OUTB [InDifferentialPairClass('DIFF_MUX1_OUTB')] p32: maxlimit=0.254 minlimit=0.127 mostfreqgap=0.127 toplayer_mingap=0.196 toplayer_maxgap=0.196 toplayer_prefgap=0.196 toplayer_minwidth=0.109 toplayer_maxwidth=0.109 toplayer_prefwidth=0.109 midlayer4_mingap=0.201 midlayer4_maxgap=0.201 midlayer4_prefgap=0.201 midlayer4_minwidth=0.104 midlayer4_maxwidth=0.104 midlayer4_prefwidth=0.104 midlayer7_mingap=0.201 midlayer7_maxgap=0.201 midlayer7_prefgap=0.201 midlayer7_minwidth=0.104 midlayer7_maxwidth=0.104 midlayer7_prefwidth=0.104 bottomlayer_mingap=0.196 bottomlayer_maxgap=0.196 bottomlayer_prefgap=0.196 bottomlayer_minwidth=0.109 bottomlayer_maxwidth=0.109 bottomlayer_prefwidth=0.109 impedanceprofiledriven=TRUE impedanceprofileid={E6B00C31-4C8E-439C-824F-D2B2CDC26F9C} impedanceprofilevalue=90.000000 maxuncoupledlength=12.7
DiffPairsRouting DIFF_ROUTE_MUX2_OUTA [InDifferentialPairClass('DIFF_MUX2_OUTA')] p33: maxlimit=0.254 minlimit=0.127 mostfreqgap=0.127 toplayer_mingap=0.196 toplayer_maxgap=0.196 toplayer_prefgap=0.196 toplayer_minwidth=0.109 toplayer_maxwidth=0.109 toplayer_prefwidth=0.109 midlayer4_mingap=0.201 midlayer4_maxgap=0.201 midlayer4_prefgap=0.201 midlayer4_minwidth=0.104 midlayer4_maxwidth=0.104 midlayer4_prefwidth=0.104 midlayer7_mingap=0.201 midlayer7_maxgap=0.201 midlayer7_prefgap=0.201 midlayer7_minwidth=0.104 midlayer7_maxwidth=0.104 midlayer7_prefwidth=0.104 bottomlayer_mingap=0.196 bottomlayer_maxgap=0.196 bottomlayer_prefgap=0.196 bottomlayer_minwidth=0.109 bottomlayer_maxwidth=0.109 bottomlayer_prefwidth=0.109 impedanceprofiledriven=TRUE impedanceprofileid={E6B00C31-4C8E-439C-824F-D2B2CDC26F9C} impedanceprofilevalue=90.000000 maxuncoupledlength=12.7
DiffPairsRouting DIFF_ROUTE_MUX2_OUTB [InDifferentialPairClass('DIFF_MUX2_OUTB')] p34: maxlimit=0.254 minlimit=0.127 mostfreqgap=0.127 toplayer_mingap=0.196 toplayer_maxgap=0.196 toplayer_prefgap=0.196 toplayer_minwidth=0.109 toplayer_maxwidth=0.109 toplayer_prefwidth=0.109 midlayer4_mingap=0.201 midlayer4_maxgap=0.201 midlayer4_prefgap=0.201 midlayer4_minwidth=0.104 midlayer4_maxwidth=0.104 midlayer4_prefwidth=0.104 midlayer7_mingap=0.201 midlayer7_maxgap=0.201 midlayer7_prefgap=0.201 midlayer7_minwidth=0.104 midlayer7_maxwidth=0.104 midlayer7_prefwidth=0.104 bottomlayer_mingap=0.196 bottomlayer_maxgap=0.196 bottomlayer_prefgap=0.196 bottomlayer_minwidth=0.109 bottomlayer_maxwidth=0.109 bottomlayer_prefwidth=0.109 impedanceprofiledriven=TRUE impedanceprofileid={E6B00C31-4C8E-439C-824F-D2B2CDC26F9C} impedanceprofilevalue=90.000000 maxuncoupledlength=12.7
Height [All] p1: minheight=0 maxheight=30 prefheight=12.7
HoleSize [All] p1: absolutevalues=TRUE maxlimit=30 minlimit=0.1 maxpercent=80.000 minpercent=20.000
HoleToHoleClearance HoleToHoleClearance_uVIA_L1_L2 [InDrillLayerPair('[uVia] TOP_L1 - L2')] p1: gap=0.25 allowstackedmicrovias=TRUE
HoleToHoleClearance HoleToHoleClearance_uVIA_L2_L3 [InDrillLayerPair('[uVia] L2 - L3')] p2: gap=0.25 allowstackedmicrovias=TRUE
HoleToHoleClearance HoleToHoleClearance_uVIA_L8_L9 [InDrillLayerPair('[uVia] L8 - L9')] p3: gap=0.25 allowstackedmicrovias=TRUE
HoleToHoleClearance HoleToHoleClearance_uVIA_L9_L10 [InDrillLayerPair('[uVia] L9 - BOTTOM_L10')] p4: gap=0.25 allowstackedmicrovias=TRUE
HoleToHoleClearance HoleToHoleClearance_L3_L8 [InDrillLayerPair('L3 - L8')] p5: gap=0.254 allowstackedmicrovias=TRUE
HoleToHoleClearance HoleToHoleClearance_L1_L10 [InDrillLayerPair('TOP_L1 - BOTTOM_L10')] p6: gap=0.4 allowstackedmicrovias=TRUE
MatchedLengths MatchedLengths_ETHPHY [InDifferentialPairClass('DIFF_ETHPHY')] p1: tolerance=0.1 checknetsindiffpair=FALSE checkdiffpairvsdiffpair=TRUE checkxsignals=TRUE checkothers=TRUE
MatchedLengths MatchedLengths_ETHPHY_1 [InDifferentialPairClass('DIFF_ETHPHY')] p2: tolerance=0.1 checknetsindiffpair=TRUE checkdiffpairvsdiffpair=FALSE checkxsignals=FALSE checkothers=FALSE
MatchedLengths MatchedLengths_HDMI [InDifferentialPairClass('DIFF_HDMI')] p3: tolerance=0.1 checknetsindiffpair=FALSE checkdiffpairvsdiffpair=TRUE checkxsignals=TRUE checkothers=TRUE
MatchedLengths MatchedLengths_HDMI_1 [InDifferentialPairClass('DIFF_HDMI')] p4: tolerance=0.1 checknetsindiffpair=TRUE checkdiffpairvsdiffpair=FALSE checkxsignals=FALSE checkothers=FALSE
MatchedLengths MatchedLengths_MD_CSI0 [InDifferentialPairClass('DIFF_MD_CSI0')] p5: tolerance=0.1 checknetsindiffpair=FALSE checkdiffpairvsdiffpair=TRUE checkxsignals=TRUE checkothers=TRUE
MatchedLengths MatchedLengths_MD_CSI0_1 [InDifferentialPairClass('DIFF_MD_CSI0')] p6: tolerance=0.1 checknetsindiffpair=TRUE checkdiffpairvsdiffpair=FALSE checkxsignals=FALSE checkothers=FALSE
MatchedLengths MatchedLengths_MD_CSI1 [InDifferentialPairClass('DIFF_MD_CSI1')] p7: tolerance=0.1 checknetsindiffpair=FALSE checkdiffpairvsdiffpair=TRUE checkxsignals=TRUE checkothers=TRUE
MatchedLengths MatchedLengths_MD_CSI1_1 [InDifferentialPairClass('DIFF_MD_CSI1')] p8: tolerance=0.1 checknetsindiffpair=TRUE checkdiffpairvsdiffpair=FALSE checkxsignals=FALSE checkothers=FALSE
MatchedLengths MatchedLengths_MD_CSI2 [InDifferentialPairClass('DIFF_MD_CSI2')] p9: tolerance=0.1 checknetsindiffpair=FALSE checkdiffpairvsdiffpair=TRUE checkxsignals=TRUE checkothers=TRUE
MatchedLengths MatchedLengths_MD_CSI2_1 [InDifferentialPairClass('DIFF_MD_CSI2')] p10: tolerance=0.1 checknetsindiffpair=TRUE checkdiffpairvsdiffpair=FALSE checkxsignals=FALSE checkothers=FALSE
MatchedLengths MatchedLengths_MD_DSI0 [InDifferentialPairClass('DIFF_MD_DSI0')] p11: tolerance=0.1 checknetsindiffpair=FALSE checkdiffpairvsdiffpair=TRUE checkxsignals=TRUE checkothers=TRUE
MatchedLengths MatchedLengths_MD_DSI0_1 [InDifferentialPairClass('DIFF_MD_DSI0')] p12: tolerance=0.1 checknetsindiffpair=TRUE checkdiffpairvsdiffpair=FALSE checkxsignals=FALSE checkothers=FALSE
MatchedLengths MatchedLengths_MD_EDP [InDifferentialPairClass('DIFF_MD_EDP')] p13: tolerance=0.1 checknetsindiffpair=FALSE checkdiffpairvsdiffpair=TRUE checkxsignals=TRUE checkothers=TRUE
MatchedLengths MatchedLengths_MD_EDP_1 [InDifferentialPairClass('DIFF_MD_EDP')] p14: tolerance=0.1 checknetsindiffpair=TRUE checkdiffpairvsdiffpair=FALSE checkxsignals=FALSE checkothers=FALSE
MatchedLengths MatchedLengths_MD_PCIE0_1 [InDifferentialPairClass('DIFF_MD_PCIE0')] p15: tolerance=0.1 checknetsindiffpair=TRUE checkdiffpairvsdiffpair=FALSE checkxsignals=FALSE checkothers=FALSE
MatchedLengths MatchedLengths_MD_PCIE1_1 [InDifferentialPairClass('DIFF_MD_PCIE0')] p16: tolerance=0.1 checknetsindiffpair=TRUE checkdiffpairvsdiffpair=FALSE checkxsignals=FALSE checkothers=FALSE
MatchedLengths MatchedLengths_MD_PCIE1_DOWN_1 [InDifferentialPairClass('DIFF_PCIE_DOWN1')] p17: tolerance=0.1 checknetsindiffpair=TRUE checkdiffpairvsdiffpair=FALSE checkxsignals=FALSE checkothers=FALSE
MatchedLengths MatchedLengths_MD_PCIE2_DOWN_1 [InDifferentialPairClass('DIFF_PCIE_DOWN2')] p18: tolerance=0.1 checknetsindiffpair=TRUE checkdiffpairvsdiffpair=FALSE checkxsignals=FALSE checkothers=FALSE
MatchedLengths MatchedLengths_MD_SGMII [InDifferentialPairClass('DIFF_MD_SGMII')] p19: tolerance=0.1 checknetsindiffpair=FALSE checkdiffpairvsdiffpair=TRUE checkxsignals=TRUE checkothers=TRUE
MatchedLengths MatchedLengths_MD_SGMII_1 [InDifferentialPairClass('DIFF_MD_SGMII')] p20: tolerance=0.1 checknetsindiffpair=TRUE checkdiffpairvsdiffpair=FALSE checkxsignals=FALSE checkothers=FALSE
MatchedLengths MatchedLengths_MD_USB0 [InDifferentialPairClass('DIFF_MD_USB0')] p21: tolerance=0.1 checknetsindiffpair=FALSE checkdiffpairvsdiffpair=TRUE checkxsignals=TRUE checkothers=TRUE
MatchedLengths MatchedLengths_MD_USB0_1 [InDifferentialPairClass('DIFF_MD_USB0')] p22: tolerance=0.1 checknetsindiffpair=TRUE checkdiffpairvsdiffpair=FALSE checkxsignals=FALSE checkothers=FALSE
MatchedLengths MatchedLengths_MD_USB1 [InDifferentialPairClass('DIFF_MD_USB1')] p23: tolerance=0.1 checknetsindiffpair=FALSE checkdiffpairvsdiffpair=TRUE checkxsignals=TRUE checkothers=TRUE
MatchedLengths MatchedLengths_MD_USB1_DOWN [InDifferentialPairClass('TUSB_USB1')] p24: tolerance=0.1 checknetsindiffpair=FALSE checkdiffpairvsdiffpair=TRUE checkxsignals=TRUE checkothers=TRUE
MatchedLengths MatchedLengths_MD_USB1_DOWN_1 [InDifferentialPairClass('TUSB_USB1_CAP')] p25: tolerance=0.1 checknetsindiffpair=TRUE checkdiffpairvsdiffpair=FALSE checkxsignals=FALSE checkothers=FALSE
MatchedLengths MatchedLengths_MD_USB2_DOWN [InDifferentialPairClass('TUSB_USB2')] p26: tolerance=0.1 checknetsindiffpair=FALSE checkdiffpairvsdiffpair=TRUE checkxsignals=TRUE checkothers=TRUE
MatchedLengths MatchedLengths_MD_USB2_DOWN_1 [InDifferentialPairClass('TUSB_USB2_CAP')] p27: tolerance=0.1 checknetsindiffpair=TRUE checkdiffpairvsdiffpair=FALSE checkxsignals=FALSE checkothers=FALSE
MatchedLengths MatchedLengths_MD_USB3_DOWN [InDifferentialPairClass('TUSB_USB3')] p28: tolerance=0.1 checknetsindiffpair=FALSE checkdiffpairvsdiffpair=TRUE checkxsignals=TRUE checkothers=TRUE
MatchedLengths MatchedLengths_MD_USB3_DOWN_1 [InDifferentialPairClass('TUSB_USB3_CAP')] p29: tolerance=0.1 checknetsindiffpair=TRUE checkdiffpairvsdiffpair=FALSE checkxsignals=FALSE checkothers=FALSE
MatchedLengths MatchedLengths_MD_USB4_DOWN [InDifferentialPairClass('TUSB_USB4')] p30: tolerance=0.1 checknetsindiffpair=FALSE checkdiffpairvsdiffpair=TRUE checkxsignals=TRUE checkothers=TRUE
MatchedLengths MatchedLengths_MD_USB4_DOWN_1 [InDifferentialPairClass('TUSB_USB4_CAP')] p31: tolerance=0.1 checknetsindiffpair=TRUE checkdiffpairvsdiffpair=FALSE checkxsignals=FALSE checkothers=FALSE
MatchedLengths MatchedLengths_MD_USB1_2 [InDifferentialPairClass('DIFF_MD_USB1')] p32: tolerance=0.1 checknetsindiffpair=TRUE checkdiffpairvsdiffpair=FALSE checkxsignals=FALSE checkothers=FALSE
MatchedLengths MatchedLengths_MD_MUX0_OUTA [InDifferentialPairClass('DIFF_MUX0_OUTA')] p33: tolerance=0.1 checknetsindiffpair=FALSE checkdiffpairvsdiffpair=TRUE checkxsignals=TRUE checkothers=TRUE
MatchedLengths MatchedLengths_MD_MUX0_OUTA_1 [InDifferentialPairClass('DIFF_MUX0_OUTA')] p34: tolerance=0.1 checknetsindiffpair=TRUE checkdiffpairvsdiffpair=FALSE checkxsignals=FALSE checkothers=FALSE
MatchedLengths MatchedLengths_MD_MUX0_OUTB [InDifferentialPairClass('DIFF_MUX0_OUTB')] p35: tolerance=0.1 checknetsindiffpair=FALSE checkdiffpairvsdiffpair=TRUE checkxsignals=TRUE checkothers=TRUE
MatchedLengths MatchedLengths_MD_MUX0_OUTB_1 [InDifferentialPairClass('DIFF_MUX0_OUTB')] p36: tolerance=0.1 checknetsindiffpair=TRUE checkdiffpairvsdiffpair=FALSE checkxsignals=FALSE checkothers=FALSE
MatchedLengths MatchedLengths_MD_MUX1_OUTA [InDifferentialPairClass('DIFF_MUX1_OUTA')] p37: tolerance=0.1 checknetsindiffpair=FALSE checkdiffpairvsdiffpair=TRUE checkxsignals=TRUE checkothers=TRUE
MatchedLengths MatchedLengths_MD_MUX1_OUTA_1 [InDifferentialPairClass('DIFF_MUX1_OUTA')] p38: tolerance=0.1 checknetsindiffpair=TRUE checkdiffpairvsdiffpair=FALSE checkxsignals=FALSE checkothers=FALSE
MatchedLengths MatchedLengths_MD_MUX1_OUTB [InDifferentialPairClass('DIFF_MUX1_OUTB')] p39: tolerance=0.1 checknetsindiffpair=FALSE checkdiffpairvsdiffpair=TRUE checkxsignals=TRUE checkothers=TRUE
MatchedLengths MatchedLengths_MD_MUX1_OUTB_1 [InDifferentialPairClass('DIFF_MUX1_OUTB')] p40: tolerance=0.1 checknetsindiffpair=TRUE checkdiffpairvsdiffpair=FALSE checkxsignals=FALSE checkothers=FALSE
MatchedLengths MatchedLengths_MD_MUX2_OUTA [InDifferentialPairClass('DIFF_MUX2_OUTA')] p41: tolerance=0.1 checknetsindiffpair=FALSE checkdiffpairvsdiffpair=TRUE checkxsignals=TRUE checkothers=TRUE
MatchedLengths MatchedLengths_MD_MUX2_OUTA_1 [InDifferentialPairClass('DIFF_MUX2_OUTA')] p42: tolerance=0.1 checknetsindiffpair=TRUE checkdiffpairvsdiffpair=FALSE checkxsignals=FALSE checkothers=FALSE
MatchedLengths MatchedLengths_MD_MUX2_OUTB [InDifferentialPairClass('DIFF_MUX2_OUTB')] p43: tolerance=0.1 checknetsindiffpair=FALSE checkdiffpairvsdiffpair=TRUE checkxsignals=TRUE checkothers=TRUE
MatchedLengths MatchedLengths_MD_MUX2_OUTB_1 [InDifferentialPairClass('DIFF_MUX2_OUTB')] p44: tolerance=0.1 checknetsindiffpair=TRUE checkdiffpairvsdiffpair=FALSE checkxsignals=FALSE checkothers=FALSE
MatchedLengths MatchedLengths_MD_MUXCAPS_USBC [InDifferentialPairClass('DIFF_MUXCAPS_USBC')] p45: tolerance=0.1 checknetsindiffpair=FALSE checkdiffpairvsdiffpair=TRUE checkxsignals=TRUE checkothers=TRUE
MatchedLengths MatchedLengths_MD_MUXCAPS_USBC_1 [InDifferentialPairClass('DIFF_MUXCAPS_USBC')] p46: tolerance=0.1 checknetsindiffpair=TRUE checkdiffpairvsdiffpair=FALSE checkxsignals=FALSE checkothers=FALSE
MatchedLengths MatchedLengths_MD_MUX_USB [InDifferentialPairClass('DIFF_MUX_USBC')] p47: tolerance=0.1 checknetsindiffpair=FALSE checkdiffpairvsdiffpair=TRUE checkxsignals=TRUE checkothers=TRUE
MatchedLengths MatchedLengths_MD_MUX_USB_1 [InDifferentialPairClass('DIFF_MUX_USBC')] p48: tolerance=0.1 checknetsindiffpair=TRUE checkdiffpairvsdiffpair=FALSE checkxsignals=FALSE checkothers=FALSE
MinimumAnnularRing [All] p1: minimumring=0.07
PlaneConnect [All] p1: pad.planeconnectstyle=Relief pad.reliefexpansion=0.508 pad.reliefentries=4 pad.reliefconductorwidth=0.254 pad.reliefairgap=0.254 via.planeconnectstyle=Direct via.reliefexpansion=0.508 via.reliefentries=4 via.reliefconductorwidth=0.254 via.reliefairgap=0.254
PolygonConnect PolygonConnect_1 [(ObjectKind = 'Pad') And (AsMM(PadXSize_AllLayers) = 5.3) And (AsMM(PadYSize_AllLayers) = 5.3)] p1: connectstyle=Relief reliefconductorwidth=0.5 reliefentries=4 polygonreliefangle="90 Angle" airgapwidth=0.5
PolygonConnect Spacers [(ObjectKind = 'Pad') And (AsMils(PadXSize_AllLayers) = 236.22) And (AsMils(PadYSize_AllLayers) = 236.22)] p2: connectstyle=Relief reliefconductorwidth=1.5 reliefentries=4 polygonreliefangle="90 Angle" airgapwidth=0.5
PolygonConnect "SX34 SCHOTTKY" [(ObjectKind = 'Pad') And (AsMM(PadXSize_AllLayers) = 2.07) And (AsMM(PadYSize_AllLayers) = 2.06)] p3: connectstyle=Relief reliefconductorwidth=0.5 reliefentries=4 polygonreliefangle="90 Angle" airgapwidth=0.3
PolygonConnect TVS_SMB [(ObjectKind = 'Pad') And (AsMM(PadXSize_AllLayers) = 2.2) And (AsMM(PadYSize_AllLayers) = 2.5)] p4: connectstyle=Relief reliefconductorwidth=0.6 reliefentries=4 polygonreliefangle="90 Angle" airgapwidth=0.3
PolygonConnect PTC24V [(ObjectKind = 'Pad') And (AsMM(PadXSize_AllLayers) = 3.3) And (AsMM(PadYSize_AllLayers) = 1.4)] p5: connectstyle=Relief reliefconductorwidth=0.8 reliefentries=4 polygonreliefangle="90 Angle" airgapwidth=0.3
PolygonConnect PTC1812 [(ObjectKind = 'Pad') And (AsMM(X1) = 9.4) And (AsMM(Y1) = 0.7)] p6: connectstyle=Relief reliefconductorwidth=0.8 reliefentries=4 polygonreliefangle="90 Angle" airgapwidth=0.254
PolygonConnect SCREWTERMINAL [(ObjectKind = 'Pad') And (AsMM(PadXSize_AllLayers) = 2.2) And (AsMM(PadYSize_AllLayers) = 2.2)] p7: connectstyle=Relief reliefconductorwidth=0.8 reliefentries=4 polygonreliefangle="90 Angle" airgapwidth=0.254
PolygonConnect DCJACK [(ObjectKind = 'Pad') And (Component = 'J5') And (AsMM(PadXSize_AllLayers) = 4.4) And (AsMM(PadYSize_AllLayers) = 2.5)] p8: connectstyle=Relief reliefconductorwidth=1 reliefentries=4 polygonreliefangle="90 Angle" airgapwidth=0.254
PolygonConnect TP [(ObjectKind = 'Pad') And (PadShape_AllLayers = 'Rounded Rectangle') And (AsMM(PadXSize_AllLayers) = 1) And (AsMM(PadYSize_AllLayers) = 1)] p9: connectstyle=Direct reliefconductorwidth=0.6 reliefentries=4 polygonreliefangle="90 Angle" airgapwidth=0.254
PolygonConnect 1206CAPS_1 [(ObjectKind = 'Pad') And (AsMM(PadXSize_AllLayers) = 1.16) And (AsMM(PadYSize_AllLayers) = 1.82)] p10: connectstyle=Relief reliefconductorwidth=0.6 reliefentries=4 polygonreliefangle="90 Angle" airgapwidth=0.254
PolygonConnect 0201RES_POLYGON [(ObjectKind = 'Pad') And (AsMM(PadXSize_AllLayers) = 0.31) And (AsMM(PadYSize_AllLayers) = 0.34)] p11: connectstyle=Relief reliefconductorwidth=0.15 reliefentries=4 polygonreliefangle="90 Angle" airgapwidth=0.254
PolygonConnect ESD_POLYGON [(ObjectKind = 'Pad') And (Net = 'GND') And (AsMM(PadXSize_AllLayers) = 0.21) And (AsMM(PadYSize_AllLayers) = 0.32)] p12: connectstyle=Relief reliefconductorwidth=0.127 reliefentries=4 polygonreliefangle="90 Angle" airgapwidth=0.254
PolygonConnect QR_POLYGONCONNECT [(ObjectKind = 'Pad') And (Name = 'QR1-PAD')] p13: connectstyle=Direct reliefconductorwidth=0.254 reliefentries=4 polygonreliefangle="90 Angle" airgapwidth=0.254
